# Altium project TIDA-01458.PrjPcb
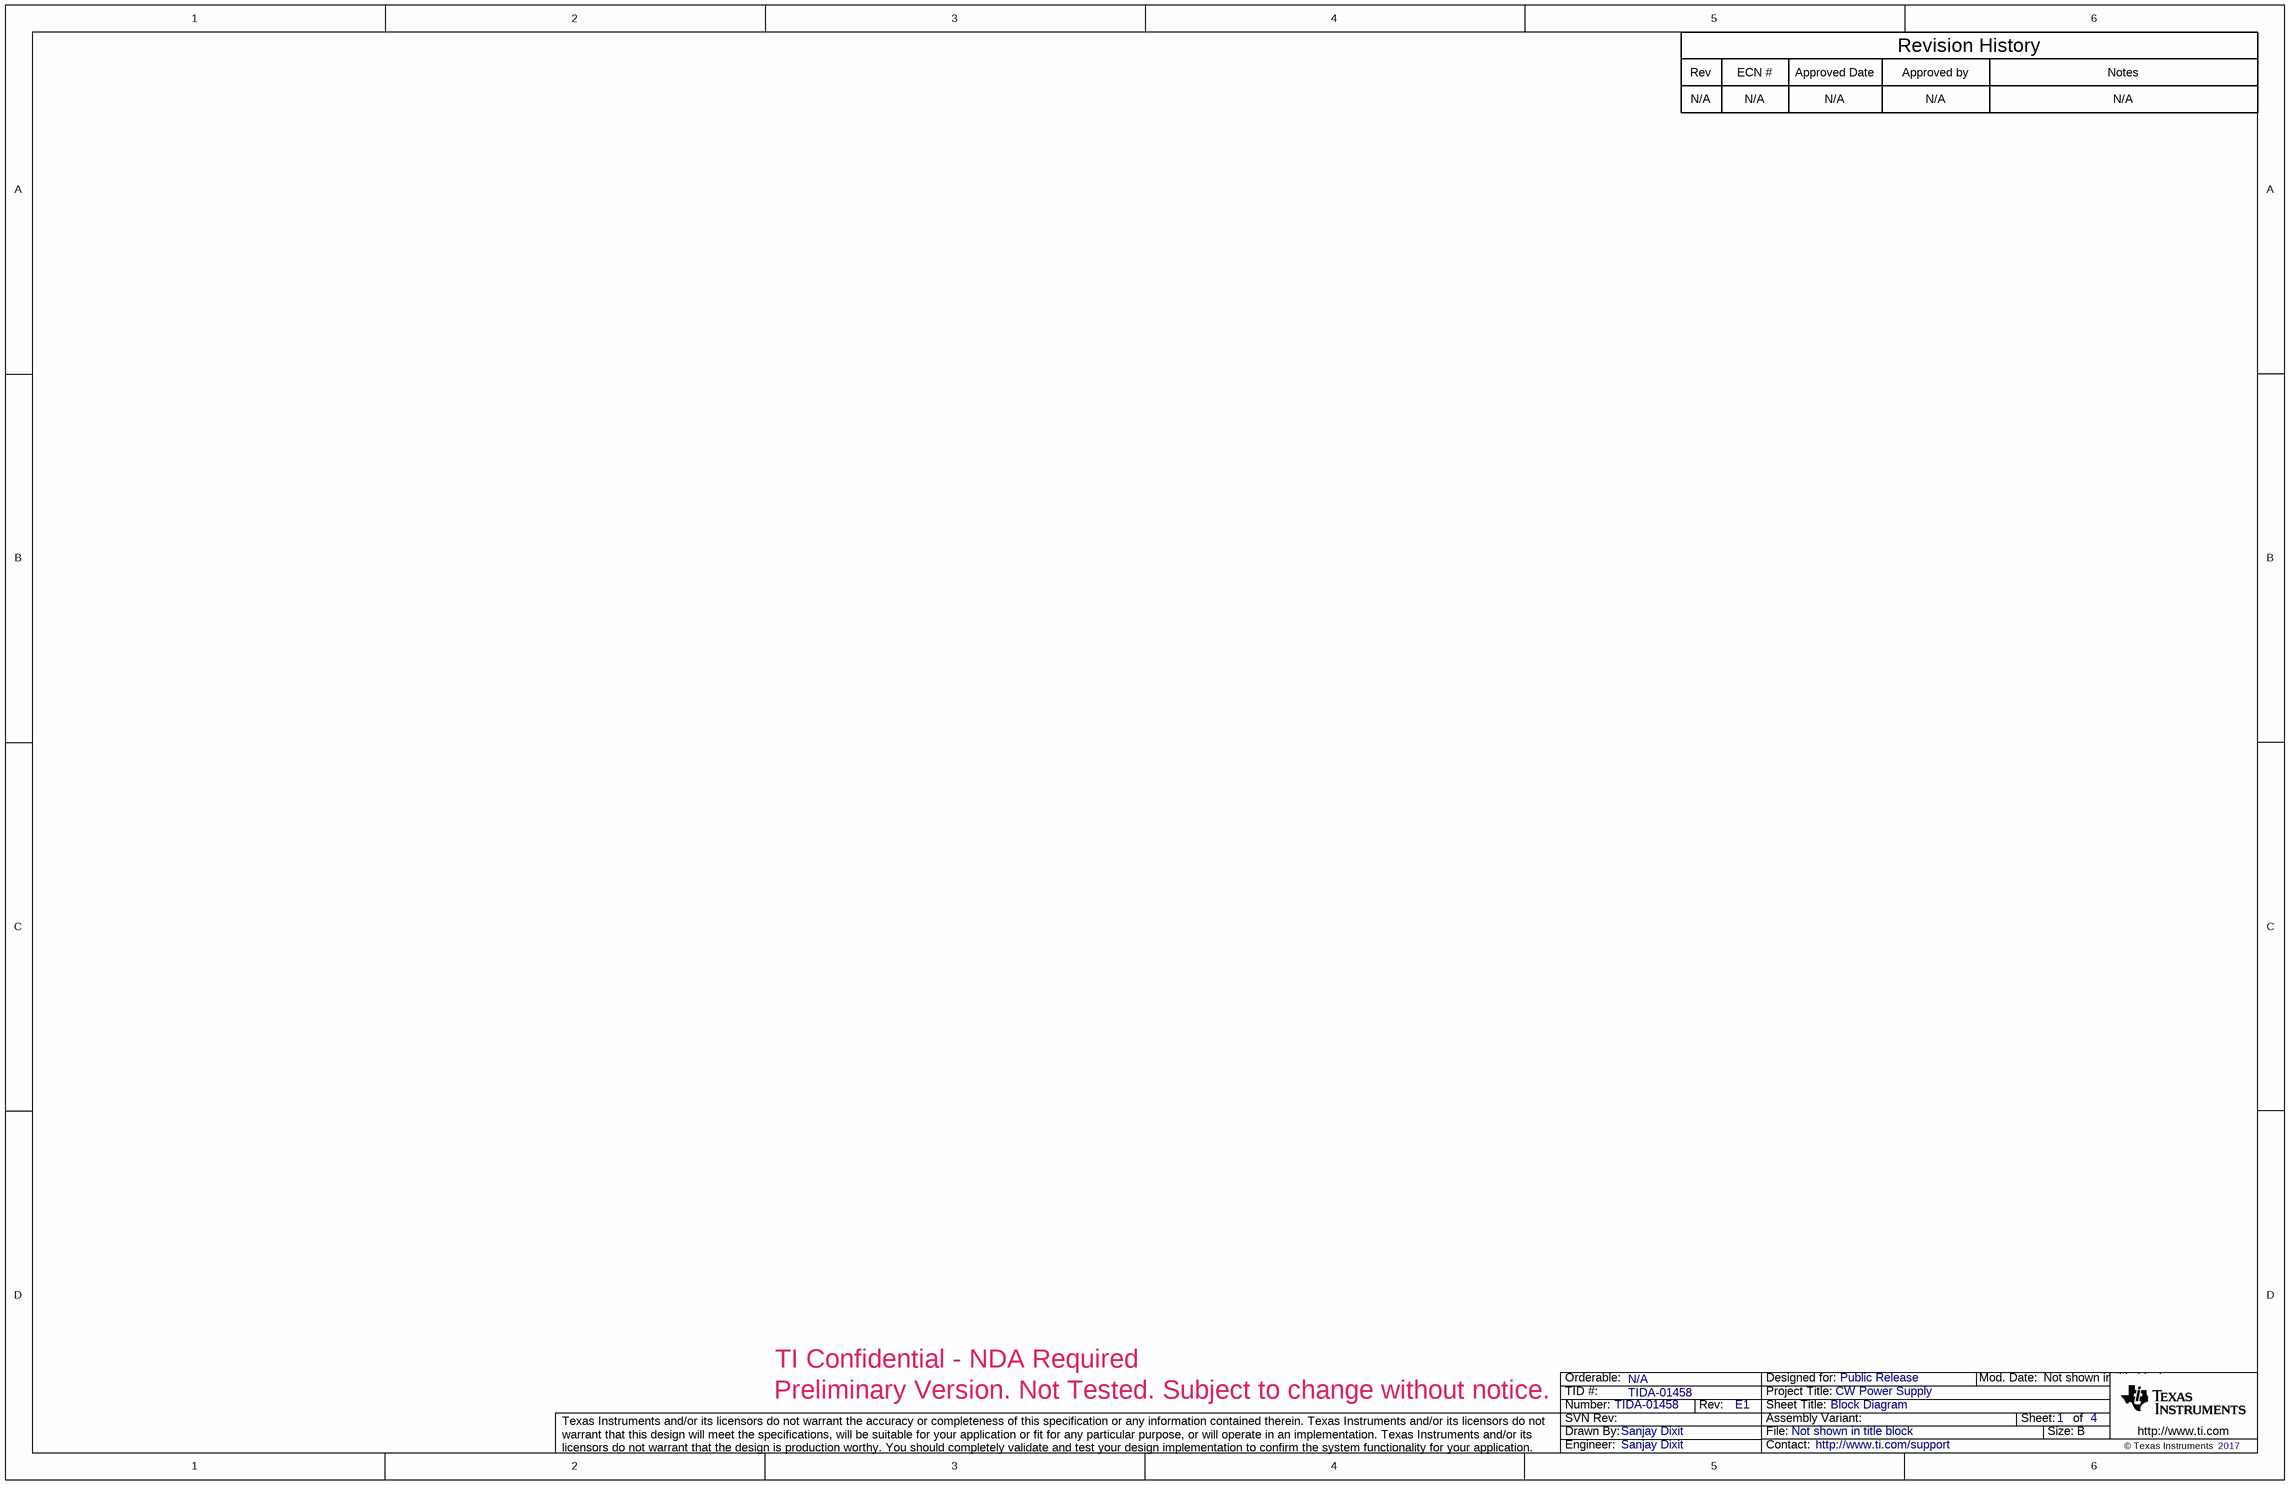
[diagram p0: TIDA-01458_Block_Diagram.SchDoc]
CopyrightYear: 2017; EVM_orderable: N/A; PCB_Layout: Akshay Labhe; PCB_Rev: E1; PRJ_Customer: Public Release; PRJ_Engineer: Sanjay Dixit; PRJ_Number: TIDA-01458; PRJ_Title: CW Power Supply; SCH_Rev: E1; TechSupport: http://www.ti.com/support; TID: TIDA-01458
4 sheets, 189 parts. Net scope: global (net labels, ports and power ports of the same name join across sheets).
Board file: TIDA-01458_PCB.PcbDoc
Sheets:
  TIDA-01458_Block_Diagram.SchDoc
  TIDA-01458-Sheet1.SchDoc
  TIDA-01458_Sheet2.SchDoc
  TIDA-01458_Hardware.SchDoc

## Sheet TIDA-01458_Block_Diagram.SchDoc: Block Diagram
size 431 x 279 mm; Date: Not shown in title block; ApprovedBy: Not shown in title block; CheckedBy: Not shown in title block; Author: Not shown in title block; CompanyName: Not shown in title block; DrawnBy: Sanjay Dixit; Engineer: Not shown in title block; Organization: Not shown in title block; Address1: Not shown in title block; Address2: Not shown in title block; Address3: Not shown in title block; Address4: Not shown in title block; DocumentNumber: 1; Revision: Use project parameter SCH_Rev; SheetNumber: 1; SheetTotal: 4; PageSetup: Record=PageOptions¦CenterHorizontal=True¦CenterVertical=True¦PrintScale=1.00¦XCorrection=1.00¦YCorrection=1.00¦PrintKind=0¦BorderSize=5000000¦LeftOffset=0¦BottomOffset=0¦Orientation=2¦PaperLength=1000¦PaperWidth=1000¦Scale=100¦PaperSource=15¦PrintQuality=600¦MediaType=1¦DitherType=10¦PaperKind=Letter¦PrintScaleMode=1

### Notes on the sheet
- Rev
- N/A
- ECN #
- Approved Date
- Approved by
- Revision History
- Notes
- TI Confidential - NDA Required
- Preliminary Version. Not Tested. Subject to change without notice.

## Sheet TIDA-01458-Sheet1.SchDoc: Sheet1
size 431 x 279 mm; Date: Not shown in title block; ApprovedBy: Not shown in title block; CheckedBy: Not shown in title block; Author: Not shown in title block; CompanyName: Not shown in title block; DrawnBy: Sanjay Dixit; Engineer: Not shown in title block; Organization: Not shown in title block; Address1: Not shown in title block; Address2: Not shown in title block; Address3: Not shown in title block; Address4: Not shown in title block; DocumentNumber: 1; Revision: Use project parameter SCH_Rev; SheetNumber: 2; SheetTotal: 4; PageSetup: Record=PageOptions¦CenterHorizontal=True¦CenterVertical=True¦PrintScale=1.00¦XCorrection=1.00¦YCorrection=1.00¦PrintKind=0¦BorderSize=5000000¦LeftOffset=0¦BottomOffset=0¦Orientation=2¦PaperLength=1000¦PaperWidth=1000¦Scale=100¦PaperSource=15¦PrintQuality=600¦MediaType=1¦DitherType=10¦PaperKind=Letter¦PrintScaleMode=1
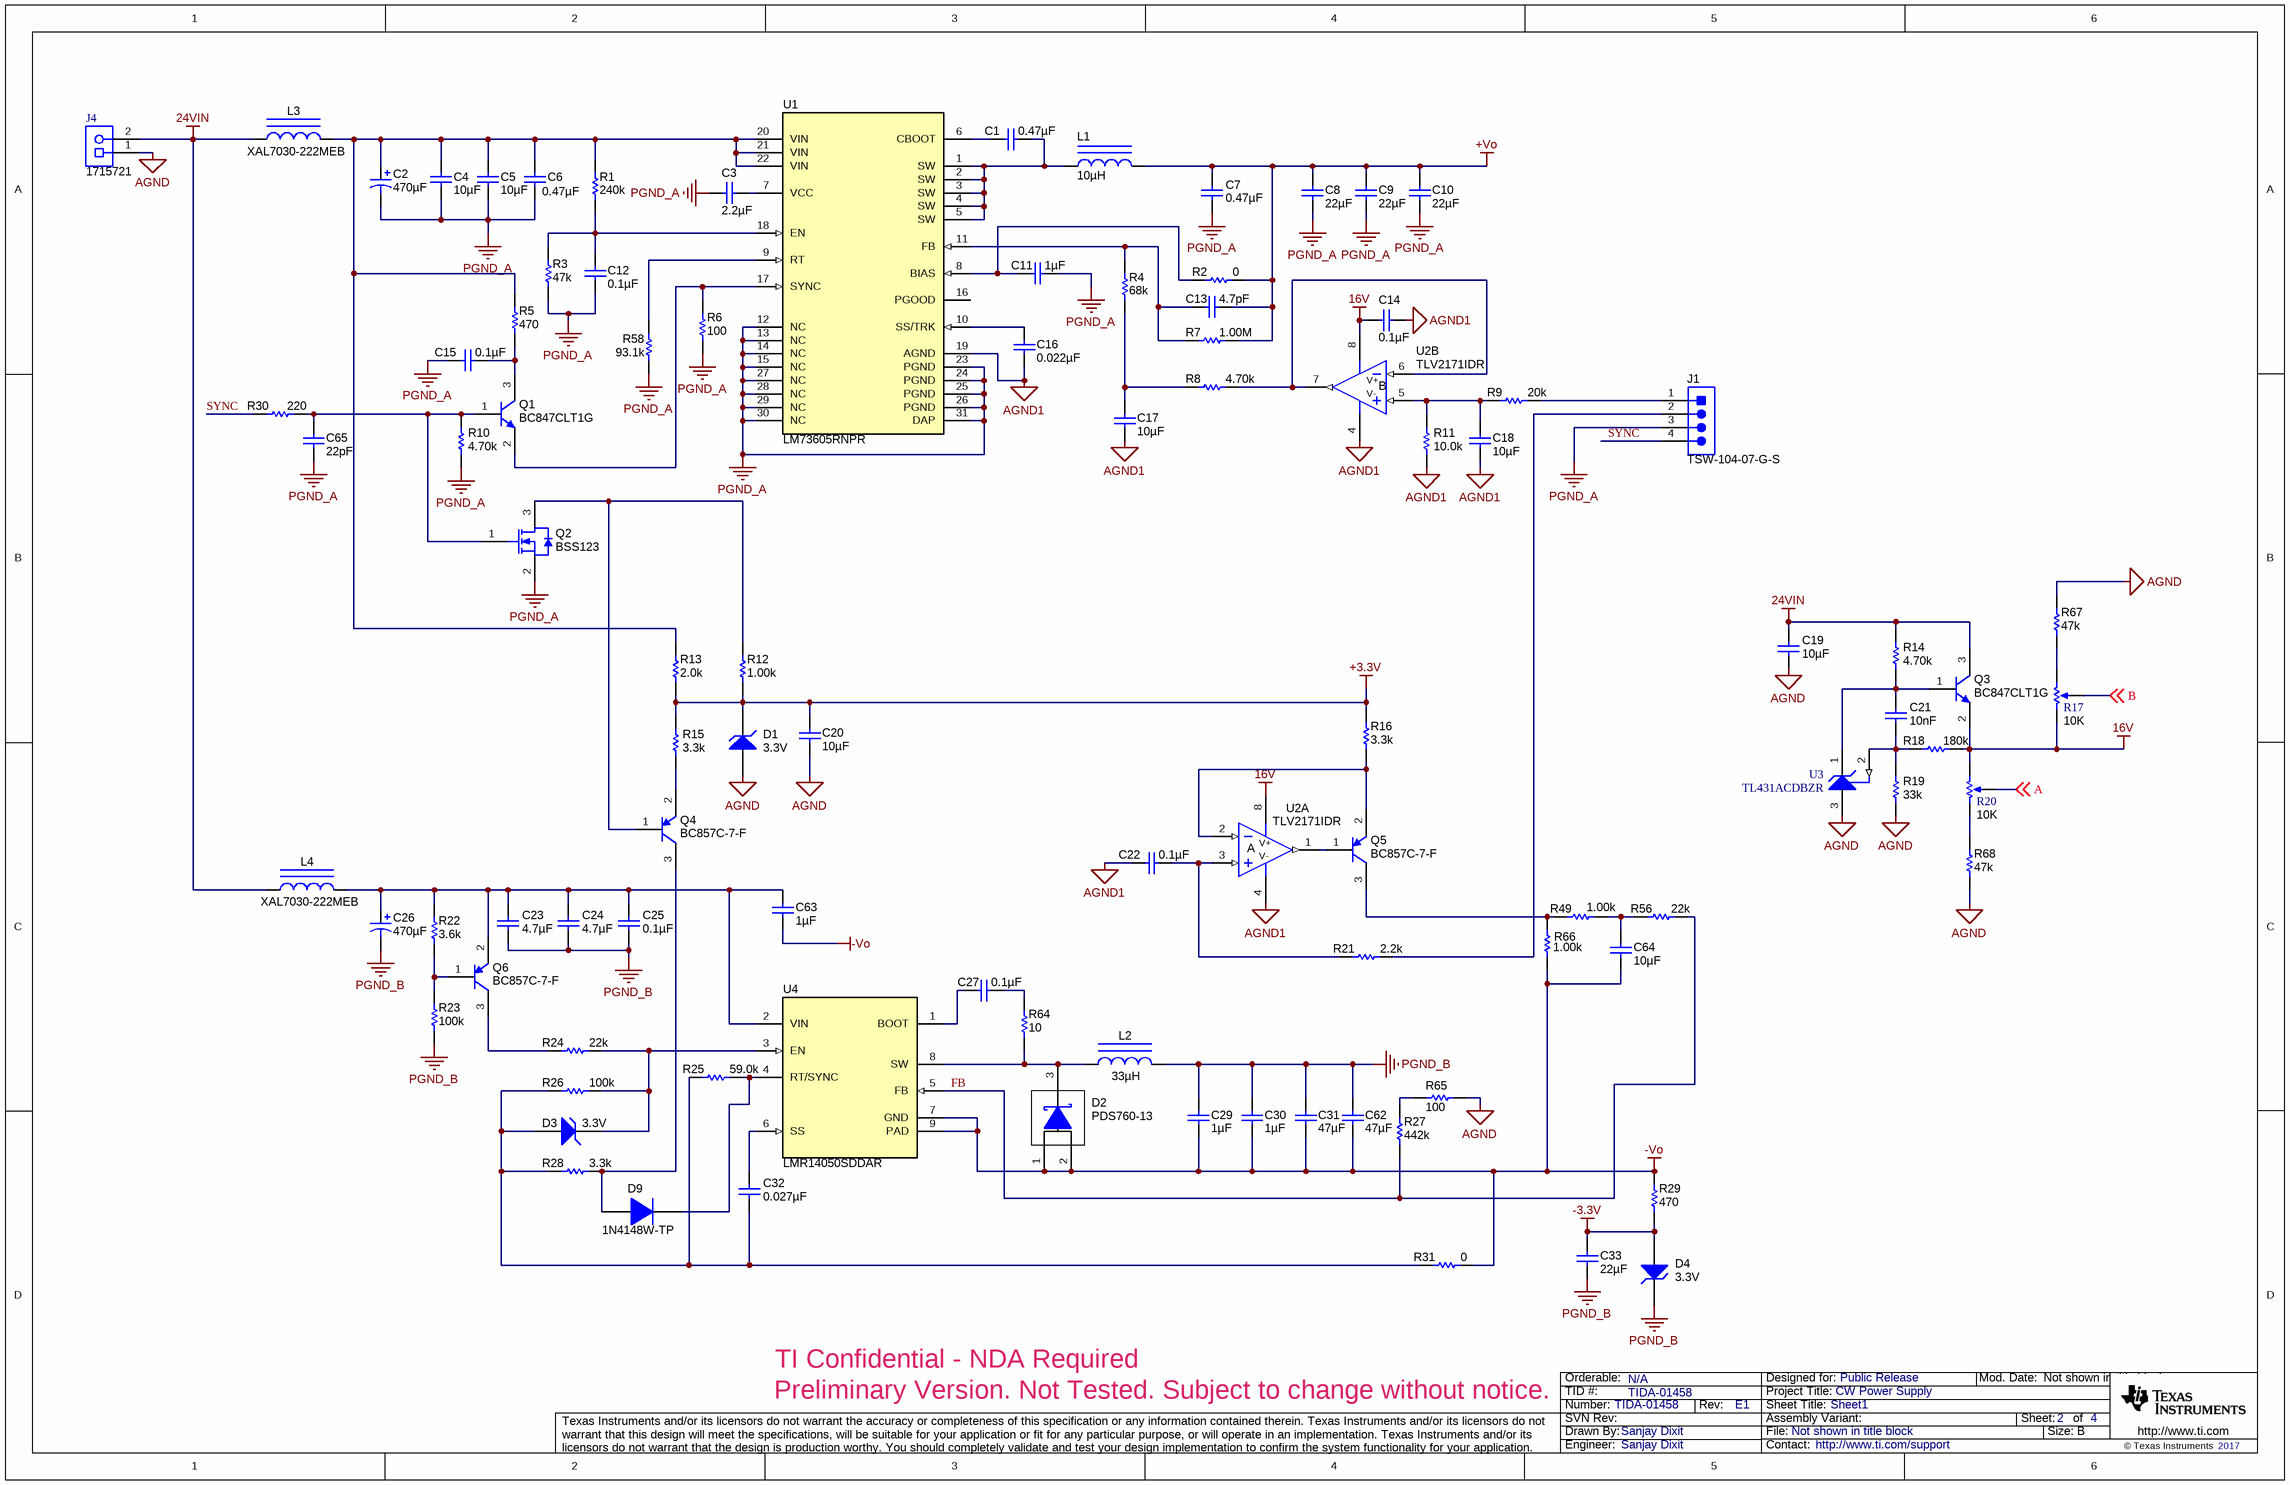
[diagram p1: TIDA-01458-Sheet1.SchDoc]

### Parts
C1  ValueDisplayed: 0.47µF  [0603]  (hidden comment: GRM188R61E474KA12D)
C2  ValueDisplayed: 470µF  [ZL_1000x2000]  (hidden comment: 35ZL470MEFC10X20)
C3  ValueDisplayed: 2.2µF  [0603]  (hidden comment: C1608X5R1V225K080AC)
C4  ValueDisplayed: 10µF  [1210_270]  (hidden comment: GRM32ER71H106KA12L)
C5  ValueDisplayed: 10µF  [1210_270]  (hidden comment: GRM32ER71H106KA12L)
C6  ValueDisplayed: 0.47µF  [0805_HV]  (hidden comment: GRM21BR71H474KA88L)
C7  ValueDisplayed: 0.47µF  [0805_HV]  (hidden comment: GRM21BR71H474KA88L)
C8  ValueDisplayed: 22µF  [1210_270]  (hidden comment: GRM32ER71E226KE15L)
C9  ValueDisplayed: 22µF  [1210_270]  (hidden comment: GRM32ER71E226KE15L)
C10  ValueDisplayed: 22µF  [1210_270]  (hidden comment: GRM32ER71E226KE15L)
C11  ValueDisplayed: 1µF  [0603]  (hidden comment: C1608X5R1H105K080AB)
C12  ValueDisplayed: 0.1µF  [0603]  (hidden comment: C1608X7R1H104K080AA)
C13  ValueDisplayed: 4.7pF  [0805_HV]  (hidden comment: 08055A4R7CAT2A)
C14  ValueDisplayed: 0.1µF  [0603]  (hidden comment: C1608X7R1H104K080AA)
C15  ValueDisplayed: 0.1µF  [0603]  (hidden comment: C1608X7R1H104K080AA)
C16  ValueDisplayed: 0.022µF  [0805_HV]  (hidden comment: 08055C223KAT2A)
C17  ValueDisplayed: 10µF  [1206_180]  (hidden comment: C3216X5R1H106K160AB)
C18  ValueDisplayed: 10µF  [1206_180]  (hidden comment: C3216X5R1H106K160AB)
C19  ValueDisplayed: 10µF  [1210_270]  (hidden comment: GRM32ER71H106KA12L)
C20  ValueDisplayed: 10µF  [1206_180]  (hidden comment: C3216X5R1H106K160AB)
C21  ValueDisplayed: 10nF  [1210_270]  (hidden comment: GRM32ER71H106KA12L)
C22  ValueDisplayed: 0.1µF  [0603]  (hidden comment: C1608X7R1H104K080AA)
C23  ValueDisplayed: 4.7µF  [1210_270]  (hidden comment: GRM32ER71H475KA88L)
C24  ValueDisplayed: 4.7µF  [1210_270]  (hidden comment: GRM32ER71H475KA88L)
C25  ValueDisplayed: 0.1µF  [0603]  (hidden comment: C1608X7R1H104K080AA)
C26  ValueDisplayed: 470µF  [ZL_1000x2000]  (hidden comment: 35ZL470MEFC10X20)
C27  ValueDisplayed: 0.1µF  [0603]  (hidden comment: C1608X7R1H104K080AA)
C29  ValueDisplayed: 1µF  [0805_HV]  (hidden comment: GRM21BR71E105KA99L)
C30  ValueDisplayed: 1µF  [0805_HV]  (hidden comment: GRM21BR71E105KA99L)
C31  ValueDisplayed: 47µF  [1206_190]  (hidden comment: C3216X5R1E476M160AC)
C32  ValueDisplayed: 0.027µF  [0603]  (hidden comment: GRM188R71E273KA01D)
C33  ValueDisplayed: 22µF  [1210_270]  (hidden comment: GRM32ER71E226KE15L)
C62  ValueDisplayed: 47µF  [1206_190]  (hidden comment: C3216X5R1E476M160AC)
C63  ValueDisplayed: 1µF  [0805_HV]  (hidden comment: GRM21BR71E105KA99L)
C64  ValueDisplayed: 10µF  [1206_180]  (hidden comment: C3216X5R1H106K160AB)
C65  ValueDisplayed: 22pF  [0603]  (hidden comment: 06035A220JAT2A)
D1  value 3.3V  [SMB]  (hidden comment: 1SMB5913BT3G)
D2  PDS760-13  [PowerDI5]
D3  value 3.3V  [SMB]  (hidden comment: 1SMB5913BT3G)
D4  value 3.3V  [SMB]  (hidden comment: 1SMB5913BT3G)
D9  1N4148W-TP  [SOD-123]
J1  TSW-104-07-G-S  [TSW-104-07-G-S]
J4  1715721  [PhoenixContact_1715721]
L1  ValueDisplayed: 10µH  [XAL7030]  (hidden comment: XAL7030-103MEB)
L2  ValueDisplayed: 33µH  [WE-HCA1]  (hidden comment: 7443551331)
L3  XAL7030-222MEB  [XAL7030]
L4  XAL7030-222MEB  [XAL7030]
Q1  BC847CLT1G  [SOT-23]
Q2  BSS123  [SOT-23]
Q3  BC847CLT1G  [SOT-23]
Q4  BC857C-7-F  [SOT-23]
Q5  BC857C-7-F  [SOT-23]
Q6  BC857C-7-F  [SOT-23]
R1  ValueDisplayed: 240k  [0805_HV]  (hidden comment: CRCW0805240KJNEA)
R2  ValueDisplayed: 0  [0603]  (hidden comment: CRCW06030000Z0EA)
R3  ValueDisplayed: 47k  [0805_HV]  (hidden comment: CRCW080547K0JNEA)
R4  ValueDisplayed: 68k  [0603]  (hidden comment: CRCW060368K0JNEA)
R5  ValueDisplayed: 470  [0603]  (hidden comment: CRCW0603470RJNEA)
R6  ValueDisplayed: 100  [0603]  (hidden comment: CRCW0603100RFKEA)
R7  ValueDisplayed: 1.00M  [0603]  (hidden comment: CRCW06031M00FKEA)
R8  ValueDisplayed: 4.70k  [0603]  (hidden comment: RC0603FR-074K7L)
R9  ValueDisplayed: 20k  [0603]  (hidden comment: CRCW060320K0JNEA)
R10  ValueDisplayed: 4.70k  [0603]  (hidden comment: RC0603FR-074K7L)
R11  ValueDisplayed: 10.0k  [0603]  (hidden comment: CRCW060310K0FKEA)
R12  ValueDisplayed: 1.00k  [0603]  (hidden comment: CRCW06031K00FKEA)
R13  ValueDisplayed: 2.0k  [0805_HV]  (hidden comment: CRCW08052K00JNEA)
R14  ValueDisplayed: 4.70k  [0603]  (hidden comment: RC0603FR-074K7L)
R15  ValueDisplayed: 3.3k  [0603]  (hidden comment: CRCW06033K30JNEA)
R16  ValueDisplayed: 3.3k  [0603]  (hidden comment: CRCW06033K30JNEA)
R17  value 10K  [Bourns_TC33X-2]  (hidden comment: TC33X-2-103E)
R18  ValueDisplayed: 180k  [0603]  (hidden comment: CRCW0603180KJNEA)
R19  ValueDisplayed: 33k  [0603]  (hidden comment: CRCW060333K0JNEA)
R20  value 10K  [Bourns_TC33X-2]  (hidden comment: TC33X-2-103E)
R21  ValueDisplayed: 2.2k  [0603]  (hidden comment: CRCW06032K20JNEA)
R22  ValueDisplayed: 3.6k  [0603]  (hidden comment: CRCW06033K60JNEA)
R23  ValueDisplayed: 100k  [0603]  (hidden comment: CRCW0603100KFKEA)
R24  ValueDisplayed: 22k  [0603]  (hidden comment: CRCW060322K0JNEA)
R25  ValueDisplayed: 59.0k  [0603]  (hidden comment: CRCW060359K0FKEA)
R26  ValueDisplayed: 100k  [0603]  (hidden comment: CRCW0603100KFKEA)
R27  ValueDisplayed: 442k  [0603]  (hidden comment: CRCW0603442KFKEA)
R28  ValueDisplayed: 3.3k  [0603]  (hidden comment: CRCW06033K30JNEA)
R29  ValueDisplayed: 470  [0805_HV]  (hidden comment: CRCW0805470RJNEA)
R30  ValueDisplayed: 220  [0603]  (hidden comment: CRCW0603220RJNEA)
R31  ValueDisplayed: 0  [0603]  (hidden comment: CRCW06030000Z0EA)
R49  ValueDisplayed: 1.00k  [0603]  (hidden comment: CRCW06031K00FKEA)
R56  ValueDisplayed: 22k  [0603]  (hidden comment: CRCW060322K0JNEA)
R58  ValueDisplayed: 93.1k  [0603]  (hidden comment: CRCW060393K1FKEA)
R64  ValueDisplayed: 10  [0603]  (hidden comment: CRCW060310R0JNEA)
R65  ValueDisplayed: 100  [0603]  (hidden comment: CRCW0603100RFKEA)
R66  ValueDisplayed: 1.00k  [0603]  (hidden comment: CRCW06031K00FKEA)
R67  ValueDisplayed: 47k  [0805_HV]  (hidden comment: CRCW080547K0JNEA)
R68  ValueDisplayed: 47k  [0805_HV]  (hidden comment: CRCW080547K0JNEA)
U1  LM73605RNPR  [RNP0030A]
U2  TLV2171IDR  [D0008A_N]  (parts A,B of 2)
U3  TL431ACDBZR  [DBZ0003A_N]
U4  LMR14050SDDAR  [DDA0008E_N]

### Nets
16V: C14.1 Q3.2(E) R17.3(CW) R18.2 R20.1(CCW) U2.8(V+)
24VIN: C19.1 J4.2 L3.1 L4.1 Q3.3(C) R14.2
+3.3V: C20.1 D1.1(K) R12.1 R13.1 R15.2 R16.2
+Vo: C7.2 C8.1 C9.1 C10.1 C13.2 L1.2 R2.1 R7.1
-3.3V: C33.1 D4.2(A) R29.1
-Vo: C29.2 C30.2 C31.2 C62.2 C63.2 C64.2 D2.1(A) D2.2(A) R29.2 R31.1 R66.1 U4.7(GND) U4.9(PAD)
AGND: C19.2 C20.2 D1.2(A) J4.1 R19.1 R65.2 R67.2 R68.1 U3.3(ANODE)
AGND1: C14.2 C16.1 C17.2 C18.2 C22.2 R11.1 U1.19(AGND) U2.4(V-)
PGND_A: C2.2(-) C3.1 C4.1 C5.1 C6.1 C7.1 C8.2 C9.2 C10.2 C11.1 C12.2 C15.2 C65.2 J1.3 Q2.2(S) R3.1 R6.1 R10.1 R58.2 U1.12(NC) U1.13(NC) U1.14(NC) U1.15(NC) U1.23(PGND) U1.24(PGND) U1.25(PGND) U1.26(PGND) U1.27(NC) U1.28(NC) U1.29(NC) U1.30(NC) U1.31(DAP)
PGND_B: C23.2 C24.2 C25.2 C26.2(-) C29.1 C30.1 C31.1 C33.2 C62.1 D4.1(K) L2.2 R23.1
A: R20.2(WIPER) ; off-sheet A
B: R17.2(WIPER) ; off-sheet B
FB: R27.1 R56.2 U4.5(FB)
SYNC: J1.4 R30.1
NetC1_1: C1.1 L1.1 U1.1(SW) U1.2(SW) U1.3(SW) U1.4(SW) U1.5(SW)
NetC1_2: C1.2 U1.6(CBOOT)
NetC2_1: C2.1(+) C4.2 C5.2 C6.2 L3.2 R1.2 R5.2 R13.2 U1.20(VIN) U1.21(VIN) U1.22(VIN)
NetC3_2: C3.2 U1.7(VCC)
NetC11_2: C11.2 R2.2 U1.8(BIAS)
NetC12_1: C12.1 R1.1 R3.2 U1.18(EN)
NetC13_1: C13.1 R4.2 R7.2 U1.11(FB)
NetC15_1: C15.1 Q1.3(C) R5.1
NetC16_2: C16.2 U1.10(SS/TRK)
NetC17_1: C17.1 R4.1 R8.2
NetC18_1: C18.1 R9.2 R11.2 U2.5(IN+)
NetC21_1: C21.1 Q3.1(B) R14.1 U3.1(CATHODE)
NetC21_2: C21.2 R18.1 R19.2 U3.2(REF)
NetC22_1: C22.1 R21.1 U2.3(IN+)
NetC23_1: C23.1 C24.1 C25.1 C26.1(+) C63.1 L4.2 Q6.2(E) R22.2 U4.2(VIN)
NetC27_1: C27.1 R64.2
NetC27_2: C27.2 U4.1(BOOT)
NetC32_1: C32.1 U4.6(SS)
NetC32_2: C32.2 D3.2(A) R25.1 R26.2 R28.1 R31.2
NetC64_1: C64.1 R49.2 R56.1
NetC65_1: C65.1 Q1.1(B) Q2.1(G) R10.2 R30.2
NetD2_3: D2.3(K) L2.1 R64.1 U4.8(SW)
NetD3_1: D3.1(K) R24.2 R26.1 U4.3(EN)
NetD9_1: D9.1(K) R25.2 U4.4(RT/SYNC)
NetD9_2: D9.2(A) Q4.3(C) R28.2
NetJ1_1: J1.1 R9.1
NetJ1_2: J1.2 R21.2
NetQ1_2: Q1.2(E) R6.2 U1.17(SYNC)
NetQ2_3: Q2.3(D) Q4.1(B) R12.2
NetQ4_2: Q4.2(E) R15.1
NetQ5_1: Q5.1(B) U2.1(OUT)
NetQ5_2: Q5.2(E) R16.1 U2.2(IN-)
NetQ5_3: Q5.3(C) R49.1 R66.2
NetQ6_1: Q6.1(B) R22.1 R23.2
NetQ6_3: Q6.3(C) R24.1
NetR8_1: R8.1 U2.6(IN-) U2.7(OUT)
NetR17_1: R17.1(CCW) R67.1
NetR20_3: R20.3(CW) R68.2
NetR27_2: R27.2 R65.1
NetR58_1: R58.1 U1.9(RT)

Not connected (* = marked no-connect by the designer): U1 16(PGOOD)

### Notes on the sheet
- TI Confidential - NDA Required
- Preliminary Version. Not Tested. Subject to change without notice.

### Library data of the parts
C1 = GRM188R61E474KA12D: CAP, CERM, 0.47 µF, 25 V, +/- 10%, X5R, 0603; Manufacturer: MuRata; Polarized: N; CompType: Capacitor; Value: 0.47uF; U/M: EA; Cap_F: 0.00000047; Tolerance_%: 10; Value1: Unknown; VDC_V: 25; Value2: 25V; TaMin_C: -55; TaMax_C: 85; SizeArea_mm2: 1.28; SizeAreaWB_mm2: 4.68; SizeX_mm: 1.6; SizeY_mm: 0.8; SizeZ_mm: 1; AEC Category: Q200
C2 C26 = 35ZL470MEFC10X20: CAP, AL, 470 µF, 35 V, +/- 20%, TH; Manufacturer: Rubycon; Polarized: Y; CompType: Capacitor; Value: 470uF; U/M: EA; Cap_F: 0.00047; Tolerance_%: 20; Value1: Unknown; VDC_V: 35; Value2: 35V; TaMin_C: -40; TaMax_C: 105; Cap_Case: 10x20; SizeAreaWB_mm2: 144; SizeArea_mm2: 100; SizeX_mm: 10; SizeZ_mm: 22; AEC Category: Q200; AEC Qualified: N; Green_Lifecycle: Not Set; Green_REACh: Incomplete
C3 = C1608X5R1V225K080AC: CAP, CERM, 2.2 µF, 35 V, +/- 10%, X5R, 0603; Manufacturer: TDK; Polarized: N; CompType: Capacitor; Value: 2.2uF; U/M: EA; Cap_F: 0.0000022; Tolerance_%: 10; ESR_ohm: 0.007674; Value1: 0.007674 ohm; VDC_V: 35; Value2: 35V; IRMS_A: 1.87823; TaMin_C: -55; TaMax_C: 85; SizeArea_mm2: 1.28; SizeAreaWB_mm2: 4.68; SizeX_mm: 1.6; SizeY_mm: 0.8; SizeZ_mm: 1; AEC Category: Q200; Green_Lifecycle: Active; Green_REACh: Passed
C4 C5 C19 C21 = GRM32ER71H106KA12L: CAP, CERM, 10 µF, 50 V, +/- 10%, X7R, 1210; Manufacturer: MuRata; Polarized: N; CompType: Capacitor; Value: 10uF; U/M: EA; Cap_F: 0.00001; Tolerance_%: 10; Value1: Unknown; VDC_V: 50; Value2: 50V; TaMin_C: -55; TaMax_C: 125; Cap_Case: 1210; SizeArea_mm2: 8; SizeAreaWB_mm2: 14.7; SizeX_mm: 3.2; SizeY_mm: 2.5; SizeZ_mm: 2.7; AEC Category: Q200
C6 C7 = GRM21BR71H474KA88L: CAP, CERM, 0.47 µF, 50 V, +/- 10%, X7R, 0805; Manufacturer: MuRata; Polarized: N; CompType: Capacitor; Value: 0.47uF; U/M: EA; Cap_F: 0.00000047; Tolerance_%: 10; Value1: Unknown; VDC_V: 50; Value2: 50V; TaMin_C: -55; TaMax_C: 125; Cap_Case: 0805; SizeArea_mm2: 2.5; SizeAreaWB_mm2: 6.75; SizeX_mm: 2; SizeY_mm: 1.25; SizeZ_mm: 1.45; AEC Category: Q200
C8-C10 C33 = GRM32ER71E226KE15L: CAP, CERM, 22 µF, 25 V, +/- 10%, X7R, 1210; Manufacturer: MuRata; Polarized: N; CompType: Capacitor; Value: 22uF; U/M: EA; Cap_F: 0.000022; Tolerance_%: 10; ESR_ohm: 0.002334; Value1: 0.002334 ohm; VDC_V: 25; Value2: 25V; IRMS_A: 3.832999; TaMin_C: -55; TaMax_C: 125; Cap_Case: 1210; SizeArea_mm2: 8; SizeAreaWB_mm2: 14.7; SizeX_mm: 3.2; SizeY_mm: 2.5; SizeZ_mm: 2.7; AEC Category: Q200; Green_Lifecycle: Active; Green_REACh: Passed
C11 = C1608X5R1H105K080AB: CAP, CERM, 1 µF, 50 V, +/- 10%, X5R, 0603; Manufacturer: TDK; Polarized: N; CompType: Capacitor; Value: 1uF; U/M: EA; Cap_F: 0.000001; Tolerance_%: 10; ESR_ohm: 0.005522; Value1: 0.005522 ohm; VDC_V: 50; Value2: 50V; IRMS_A: 2.21617; TaMin_C: -55; TaMax_C: 85; SizeArea_mm2: 1.28; SizeAreaWB_mm2: 4.68; SizeX_mm: 1.6; SizeY_mm: 0.8; SizeZ_mm: 1; AEC Category: Q200
C12 C14 C15 C22 C25 C27 = C1608X7R1H104K080AA: CAP, CERM, 0.1 µF, 50 V, +/- 10%, X7R, 0603; Manufacturer: TDK; Polarized: N; CompType: Capacitor; Value: 0.1uF; U/M: EA; Cap_F: 0.0000001; Tolerance_%: 10; ESR_ohm: 0.0296; Value1: 0.0296 ohm; VDC_V: 50; Value2: 50V; IRMS_A: 0.97199; TaMin_C: -55; TaMax_C: 125; SizeArea_mm2: 1.28; SizeAreaWB_mm2: 4.68; SizeX_mm: 1.6; SizeY_mm: 0.8; SizeZ_mm: 1; AEC Category: Q200
C13 = 08055A4R7CAT2A: CAP, CERM, 4.7 pF, 50 V, +/- 5%, C0G/NP0, 0805; Manufacturer: AVX; Polarized: N; CompType: Capacitor; Value: 4.7pF; U/M: EA; Cap_F: 0.0000000000047; Tolerance_%: 5; ESR_ohm: 2.668; Value1: 2.668 ohm; VDC_V: 50; Value2: 50V; TaMin_C: -55; TaMax_C: 125; Cap_Case: 0805; SizeArea_mm2: 2.5; SizeAreaWB_mm2: 6.75; SizeX_mm: 2; SizeY_mm: 1.25; SizeZ_mm: 1.45; AEC Category: Q200
C16 = 08055C223KAT2A: CAP, CERM, 0.022 µF, 50 V, +/- 10%, X7R, 0805; Manufacturer: AVX; Polarized: N; CompType: Capacitor; Value: 0.022uF; U/M: EA; Cap_F: 0.000000022; Tolerance_%: 10; ESR_ohm: 0.052; Value1: 0.052 ohm; VDC_V: 50; Value2: 50V; TaMin_C: -55; TaMax_C: 125; Cap_Case: 0805; AEC Category: Q200
C17 C18 C20 C64 = C3216X5R1H106K160AB: CAP, CERM, 10 µF, 50 V,+/- 10%, X5R, 1206; Manufacturer: TDK; Polarized: N; CompType: Capacitor; Value: 10uF; U/M: EA; Cap_F: 0.00001; Tolerance_%: 10; ESR_ohm: 0.002229; Value1: 0.002229 ohm; VDC_V: 50; Value2: 50V; IRMS_A: 4.85932; TaMin_C: -55; TaMax_C: 85; Cap_Case: 1206; SizeArea_mm2: 5.12; SizeAreaWB_mm2: 10.92; SizeX_mm: 3.2; SizeY_mm: 1.6; SizeZ_mm: 1.8; AEC Category: Q200; Green_Lifecycle: Active; Green_REACh: Passed
C23 C24 = GRM32ER71H475KA88L: CAP, CERM, 4.7 µF, 50 V, +/- 10%, X7R, 1210; Manufacturer: MuRata; Polarized: N; CompType: Capacitor; Value: 4.7uF; U/M: EA; Cap_F: 0.0000047; Tolerance_%: 10; ESR_ohm: 0.002; Value1: 0.002 ohm; VDC_V: 50; Value2: 50V; TaMin_C: -55; TaMax_C: 125; Cap_Case: 1210; SizeArea_mm2: 8; SizeAreaWB_mm2: 14.7; SizeX_mm: 3.2; SizeY_mm: 2.5; SizeZ_mm: 2.7; AEC Category: Q200
C29 C30 C63 = GRM21BR71E105KA99L: CAP, CERM, 1 µF, 25 V, +/- 10%, X7R, 0805; Manufacturer: MuRata; Polarized: N; CompType: Capacitor; Value: 1uF; U/M: EA; Cap_F: 0.000001; Tolerance_%: 10; Value1: Unknown; VDC_V: 25; Value2: 25V; TaMin_C: -55; TaMax_C: 125; Cap_Case: 0805; SizeArea_mm2: 2.5; SizeAreaWB_mm2: 6.75; SizeX_mm: 2; SizeY_mm: 1.25; SizeZ_mm: 1.45; AEC Category: Q200
C31 C62 = C3216X5R1E476M160AC: CAP, CERM, 47 µF, 25 V, +/- 20%, X5R, 1206_190; Manufacturer: TDK; Polarized: N; CompType: Capacitor; Value: 47uF; U/M: EA; Cap_F: 0.000047; Tolerance_%: 20; Value1: Unknown; VDC_V: 25; Value2: 25V; TaMin_C: -55; TaMax_C: 85; Cap_Case: 1206; SizeArea_mm2: 5.12; SizeAreaWB_mm2: 10.92; SizeX_mm: 3.2; SizeY_mm: 1.6; SizeZ_mm: 1.9; AEC Category: Q200; Green_Lifecycle: Active; Green_REACh: Passed
C32 = GRM188R71E273KA01D: CAP, CERM, 0.027 µF, 25 V, +/- 10%, X7R, 0603; Manufacturer: MuRata; Polarized: N; CompType: Capacitor; Value: 0.027uF; U/M: EA; Cap_F: 0.000000027; Tolerance_%: 10; Value1: Unknown; VDC_V: 25; Value2: 25V; TaMin_C: -55; TaMax_C: 125; SizeArea_mm2: 1.28; SizeAreaWB_mm2: 4.68; SizeX_mm: 1.6; SizeY_mm: 0.8; SizeZ_mm: 1; AEC Category: Q200
C65 = 06035A220JAT2A: CAP, CERM, 22 pF, 50 V,+/- 5%, C0G/NP0, 0603; Manufacturer: AVX; Polarized: N; CompType: Capacitor; Value: 22pF; U/M: EA; Cap_F: 0.000000000022; Tolerance_%: 5; ESR_ohm: 0.259; Value1: 0.259 ohm; VDC_V: 50; Value2: 50V; TaMin_C: -55; TaMax_C: 125; SizeArea_mm2: 1.28; SizeAreaWB_mm2: 4.68; SizeX_mm: 1.6; SizeY_mm: 0.8; SizeZ_mm: 1; AEC Category: Q200; Green_Lifecycle: Active; Green_REACh: Passed
D1 D3 D4 = 1SMB5913BT3G: Diode, Zener, 3.3 V, 550 mW, SMB; Manufacturer: ON Semiconductor; SymbolCreator: a0412235; U/M: EA; Power_W: 0.55; Vz_V: 3.3; Value1: 0.55W; RJA_CperW: 226; SizeAreaWB_mm2: 44.156; SizeArea_mm2: 21.336; SizeX_mm: 5.6; SizeY_mm: 3.81; SizeZ_mm: 2.6; AEC Category: Q101
D2 = PDS560-13: Diode, Schottky, 60 V, 7 A, PowerDI5; Manufacturer: Diodes Inc.; U/M: EA; Vf_V: 0.67; Value: 60V; Value1: 7A; Value2: 0.67V; Io_A: 5; Vr_V: 60; TJmax_C: 150; SizeAreaWB_mm2: 49.56; SizeArea_mm2: 24.96; SizeX_mm: 6.4; SizeY_mm: 3.9; SizeZ_mm: 1.05; AEC Category: Q101; Green_Lifecycle: Active; Green_REACh: Passed
D9 = 1N4148W-TP: Diode, Switching, 100 V, 0.15 A, SOD-123; Manufacturer: Micro Commercial Components; U/M: EA; Vf_V: 1.25; Value: 100V; Value1: 0.15A; Value2: 1.25V; Io_A: 0.15; Vr_V: 100; TJmax_C: 150; SizeAreaWB_mm2: 13.095; SizeArea_mm2: 6.545; SizeX_mm: 3.85; SizeY_mm: 1.7; SizeZ_mm: 1.35; AEC Category: Q101; Green_Lifecycle: Not Set; Green_REACh: Incomplete
J1 = TSW-104-07-G-S: Header, 100mil, 4x1, Gold, TH; Manufacturer: Samtec; SymbolCreator: a0412235; Pitch_mm: 2.54; Gender: Male; Shrouded: N; Row_Count: 1; Current_A: 6.3; Voltage_V: 550; Cert_CSA: Y
J4 = 1715721: Terminal Block, 5.08 mm, 2x1, TH; Manufacturer: Phoenix Contact; SymbolCreator: a0412235; Pitch_mm: 5.08; Gender: Female; Row_Count: 1; ContactFinish: Tin; Current_A: 17.5; Voltage_V: 400; Cert_CSA: Y; Cert_CULUS: N
L1 = XAL7030-103MEB: Inductor, Shielded, Composite, 10 µH, 5.3 A, 0.057 ohm, SMD; Manufacturer: Coilcraft; Value: 10uH; Ind_H: 10.0E-6; Imax_A: 5.3; Irms: 5.3A @ 40C rise; Isat: 7A @ 30% inductance drop; DCR_ohm: 0.057; Value2: 5.3A; SizeAreaWB_mm2: 100; SizeArea_mm2: 64; SizeX_mm: 8; SizeZ_mm: 3.1; AEC Category: Q200; Green_Lifecycle: Not Set; Green_REACh: Incomplete
L2 = 7443551331: Inductor, Shielded Drum Core, WE-Perm, 33uH, 5.5A, 0.0305 ohm, SMD; Manufacturer: Wurth Elektronik eiSos; Ind_H: 33.0E-6; Imax_A: 5.5; Irms: 5.5A @ 50C rise; Isat: 5.5A @ 30% inductance drop; DCR_ohm: 0.0305; U/M: EA
L3 L4 = XAL7030-222MEB: Inductor, Shielded, Composite, 2.2uH, 12.9A, 0.0137 ohm, SMD; Manufacturer: Coilcraft; ValueDisplayed: 2.2µH; Ind_H: 2.2E-6; Imax_A: 12.9; Irms: 12.9A @ 40C rise; Isat: 18A @ 0.7% inductance drop; DCR_ohm: 0.0137
Q1 Q3 = BC847CLT1G, ON Semiconductor: Transistor, NPN, 45 V, 0.1 A, SOT-23; CompType: BJT; PNP: 0; NPN: 1; Vceo_V: 45; Vcesat1_V: 0.7; Value: 45 V; IcRated_A: 0.1; Value1: 0.1 A; HfeMax: 800; TaMin_C: -55; TaMax_C: 150; SizeAreaWB_mm2: 14; SizeArea_mm2: 7.5; SizeX_mm: 2.5; SizeY_mm: 3; SizeZ_mm: 1.1; U/M: EA; AEC Category: Q101
Q2 = BSS123: MOSFET, N-CH, 100 V, 0.17 A, SOT-23; Manufacturer: Fairchild Semiconductor; Alternate Manufacturer: None; U/M: EA; ChType: N; Value: 100V; VdsMax_V: 100; Value1: 10 ohm; Rdson45_ohm: 10; Value2: 1.8 nC; QgTyp_nC: 1.8; Vgs_V: 20; IdsMax_A: 0.17; AEC Category: Q101
Q4-Q6 = BC857C-7-F, Diodes Inc.: Transistor, PNP, 45 V, 0.1 A, SOT-23; CompType: BJT; PNP: 1; NPN: 0; Vceo_V: 45; Vcesat1_V: 0.075; Value: 45 V; IcRated_A: 0.1; Value1: 0.1 A; HfeMax: 600; TaMin_C: -65; TaMax_C: 150; U/M: EA; AEC Category: Q101
R1 = CRCW0805240KJNEA: RES, 240 k, 5%, 0.125 W, 0805; Manufacturer: Vishay-Dale; CompType: Resistor; Value: 240k; Res_ohm: 240000; Tolerance_%: 5; Power_W: 0.125; Value2: 0.125W; VDC_V: 150; TempCo: 200 ppm/C; SizeArea_mm2: 2.5; SizeX_mm: 2; SizeY_mm: 1.25; SizeZ_mm: 1.45; EIA_Code: E24; U/M: EA; AEC Category: Q200
R2 R31 = CRCW06030000Z0EA: RES, 0, 5%, 0.1 W, 0603; Manufacturer: Vishay-Dale; CompType: Resistor; Value: 0; Value_Code: 0000; Tolerance_%: 5; Power_W: 0.1; Value2: 0.1W; VDC_V: 75; TempCo: 200 ppm/C; SizeArea_mm2: 1.28; SizeX_mm: 1.6; SizeY_mm: 0.8; SizeZ_mm: 1; EIA_Code: E24; U/M: EA; AEC Category: Q200; Green_Lifecycle: Active; Green_REACh: Passed
R3 R67 R68 = CRCW080547K0JNEA: RES, 47 k, 5%, 0.125 W, 0805; Manufacturer: Vishay-Dale; CompType: Resistor; Value: 47k; Res_ohm: 47000; Value_Code: 47k0; Tolerance_%: 5; Power_W: 0.125; Value2: 0.125W; VDC_V: 150; TempCo: 200 ppm/C; SizeArea_mm2: 2.5; SizeX_mm: 2; SizeY_mm: 1.25; SizeZ_mm: 1.45; EIA_Code: E24; U/M: EA; AEC Category: Q200
R4 = CRCW060368K0JNEA: RES, 68 k, 5%, 0.1 W, 0603; Manufacturer: Vishay-Dale; CompType: Resistor; Value: 68k; Res_ohm: 68000; Value_Code: 68k0; Tolerance_%: 5; Power_W: 0.1; Value2: 0.1W; VDC_V: 75; TempCo: 200 ppm/C; EIA_Code: E24; U/M: EA; AEC Category: Q200
R5 = CRCW0603470RJNEA: RES, 470, 5%, 0.1 W, 0603; Manufacturer: Vishay-Dale; CompType: Resistor; Value: 470; Value_Code: 470R; Tolerance_%: 5; Power_W: 0.1; Value2: 0.1W; VDC_V: 75; TempCo: 200 ppm/C; SizeArea_mm2: 1.28; SizeX_mm: 1.6; SizeY_mm: 0.8; SizeZ_mm: 1; EIA_Code: E24; U/M: EA; AEC Category: Q200; Green_Lifecycle: Active; Green_REACh: Passed
R6 R65 = CRCW0603100RFKEA: RES, 100, 1%, 0.1 W, 0603; Manufacturer: Vishay-Dale; CompType: Resistor; Value: 100; Value_Code: 100R; Tolerance_%: 1; Power_W: 0.1; Value2: 0.1W; VDC_V: 75; TempCo: 100 ppm/C; SizeArea_mm2: 1.28; SizeX_mm: 1.6; SizeY_mm: 0.8; EIA_Code: E96; U/M: EA; AEC Category: Q200; Green_Lifecycle: Active; Green_REACh: Passed
R7 = CRCW06031M00FKEA: RES, 1.00 M, 1%, 0.1 W, 0603; Manufacturer: Vishay-Dale; CompType: Resistor; Value: 1.00Meg; Res_ohm: 1000000; Value_Code: 1M00; Tolerance_%: 1; Power_W: 0.1; Value2: 0.1W; VDC_V: 75; TempCo: 100 ppm/C; SizeArea_mm2: 1.28; SizeX_mm: 1.6; SizeY_mm: 0.8; EIA_Code: E96; U/M: EA; AEC Category: Q200; Green_Lifecycle: Active; Green_REACh: Passed
R8 R10 R14 = RC0603FR-074K7L: RES, 4.70 k, 1%, 0.1 W, 0603; Manufacturer: Yageo America; CompType: Resistor; Value: 4.70k; Res_ohm: 4700; Value_Code: 4k70; Tolerance_%: 1; Power_W: 0.1; Value2: 0.1W; VDC_V: 150; TempCo: 200 ppm/C; SizeArea_mm2: 1.28; SizeX_mm: 1.6; SizeY_mm: 0.8; U/M: EA; AEC Category: Q200; Green_Lifecycle: Active; Green_REACh: Passed
R9 = CRCW060320K0JNEA: RES, 20 k, 5%, 0.1 W, 0603; Manufacturer: Vishay-Dale; CompType: Resistor; Value: 20k; Res_ohm: 20000; Value_Code: 20k0; Tolerance_%: 5; Power_W: 0.1; Value2: 0.1W; VDC_V: 75; TempCo: 200 ppm/C; EIA_Code: E24; U/M: EA; AEC Category: Q200
R11 = CRCW060310K0FKEA: RES, 10.0 k, 1%, 0.1 W, 0603; Manufacturer: Vishay-Dale; CompType: Resistor; Value: 10.0k; Res_ohm: 10000; Value_Code: 10k0; Tolerance_%: 1; Power_W: 0.1; Value2: 0.1W; VDC_V: 75; TempCo: 100 ppm/C; SizeArea_mm2: 1.28; SizeX_mm: 1.6; SizeY_mm: 0.8; EIA_Code: E96; U/M: EA; AEC Category: Q200; Green_Lifecycle: Active; Green_REACh: Passed
R12 R49 R66 = CRCW06031K00FKEA: RES, 1.00 k, 1%, 0.1 W, 0603; Manufacturer: Vishay-Dale; CompType: Resistor; Value: 1.00k; Res_ohm: 1000; Value_Code: 1k00; Tolerance_%: 1; Power_W: 0.1; Value2: 0.1W; VDC_V: 75; TempCo: 100 ppm/C; SizeArea_mm2: 1.28; SizeX_mm: 1.6; SizeY_mm: 0.8; EIA_Code: E96; U/M: EA; AEC Category: Q200; Green_Lifecycle: Active; Green_REACh: Passed
R13 = CRCW08052K00JNEA: RES, 2.0 k, 5%, 0.125 W, 0805; Manufacturer: Vishay-Dale; CompType: Resistor; Value: 2.0k; Res_ohm: 2000; Value_Code: 2k00; Tolerance_%: 5; Power_W: 0.125; Value2: 0.125W; VDC_V: 150; TempCo: 200 ppm/C; SizeArea_mm2: 2.5; SizeX_mm: 2; SizeY_mm: 1.25; SizeZ_mm: 1.45; EIA_Code: E24; U/M: EA; AEC Category: Q200; Green_Lifecycle: Active; Green_REACh: Passed
R15 R28 = CRCW06033K30JNEA: RES, 3.3 k, 5%, 0.1 W, 0603; Manufacturer: Vishay-Dale; CompType: Resistor; Value: 3.3k; Res_ohm: 3300; Value_Code: 3k30; Tolerance_%: 5; Power_W: 0.1; Value2: 0.1W; VDC_V: 75; TempCo: 200 ppm/C; EIA_Code: E24; U/M: EA; AEC Category: Q200
R16 = CRCW06033K30JNEA: RES, 3.3 k, 5%, 0.1 W, 0603; Manufacturer: Vishay-Dale; CompType: Resistor; Value: 3.3k; Res_ohm: 3300; Value_Code: 3k30; Tolerance_%: 5; Power_W: 0.1; Value2: 0.1W; VDC_V: 75; TempCo: 200 ppm/C; SizeArea_mm2: 1.28; SizeX_mm: 1.6; SizeY_mm: 0.8; SizeZ_mm: 1; EIA_Code: E24; U/M: EA; AEC Category: Q200; Green_Lifecycle: Active; Green_REACh: Passed
R17 R20 = TC33X-2-103E: TRIMMER 10K OHM 0.1W; Manufacturer: Bourns; Sim Note: Enter the Resistance value and the set point into parameter fields.; SymbolCreator: a0412235; CompType: Potentiometer; SizeAreaWB_mm2: 22.08; SizeArea_mm2: 13.68; SizeX_mm: 3.8; SizeY_mm: 3.6; SizeZ_mm: 1.5
R18 = CRCW0603180KJNEA: RES, 180 k, 5%, 0.1 W, 0603; Manufacturer: Vishay-Dale; CompType: Resistor; Value: 180k; Res_ohm: 180000; Tolerance_%: 5; Power_W: 0.1; Value2: 0.1W; VDC_V: 75; TempCo: 200 ppm/C; SizeArea_mm2: 1.28; SizeX_mm: 1.6; SizeY_mm: 0.8; SizeZ_mm: 1; EIA_Code: E24; U/M: EA; AEC Category: Q200
R19 = CRCW060333K0JNEA: RES, 33 k, 5%, 0.1 W, 0603; Manufacturer: Vishay-Dale; CompType: Resistor; Value: 33k; Res_ohm: 33000; Value_Code: 33k0; Tolerance_%: 5; Power_W: 0.1; Value2: 0.1W; VDC_V: 75; TempCo: 200 ppm/C; SizeArea_mm2: 1.28; SizeX_mm: 1.6; SizeY_mm: 0.8; SizeZ_mm: 1; EIA_Code: E24; U/M: EA; AEC Category: Q200; Green_Lifecycle: Active; Green_REACh: Passed
R21 = CRCW06032K20JNEA: RES, 2.2 k, 5%, 0.1 W, 0603; Manufacturer: Vishay-Dale; CompType: Resistor; Value: 2.2k; Res_ohm: 2200; Value_Code: 2k20; Tolerance_%: 5; Power_W: 0.1; Value2: 0.1W; VDC_V: 75; TempCo: 200 ppm/C; EIA_Code: E24; U/M: EA; AEC Category: Q200
R22 = CRCW06033K60JNEA: RES, 3.6 k, 5%, 0.1 W, 0603; Manufacturer: Vishay-Dale; CompType: Resistor; Value: 3.6k; Res_ohm: 3600; Value_Code: 3k60; Tolerance_%: 5; Power_W: 0.1; Value2: 0.1W; VDC_V: 75; TempCo: 200 ppm/C; SizeArea_mm2: 1.28; SizeX_mm: 1.6; SizeY_mm: 0.8; SizeZ_mm: 1; EIA_Code: E24; U/M: EA; AEC Category: Q200
R23 R26 = CRCW0603100KFKEA: RES, 100 k, 1%, 0.1 W, 0603; Manufacturer: Vishay-Dale; CompType: Resistor; Value: 100k; Res_ohm: 100000; Tolerance_%: 1; Power_W: 0.1; Value2: 0.1W; VDC_V: 75; TempCo: 100 ppm/C; SizeArea_mm2: 1.28; SizeX_mm: 1.6; SizeY_mm: 0.8; EIA_Code: E96; U/M: EA; AEC Category: Q200; Green_Lifecycle: Active; Green_REACh: Passed
R24 = CRCW060322K0JNEA: RES, 22 k, 5%, 0.1 W, 0603; Manufacturer: Vishay-Dale; CompType: Resistor; Value: 22k; Res_ohm: 22000; Value_Code: 22k0; Tolerance_%: 5; Power_W: 0.1; Value2: 0.1W; VDC_V: 75; TempCo: 200 ppm/C; EIA_Code: E24; U/M: EA; AEC Category: Q200
R25 = CRCW060359K0FKEA: RES, 59.0 k, 1%, 0.1 W, 0603; Manufacturer: Vishay-Dale; CompType: Resistor; Value: 59.0k; Res_ohm: 59000; Value_Code: 59k0; Tolerance_%: 1; Power_W: 0.1; Value2: 0.1W; VDC_V: 75; TempCo: 100 ppm/C; SizeArea_mm2: 1.28; SizeX_mm: 1.6; SizeY_mm: 0.8; EIA_Code: E96; U/M: EA; AEC Category: Q200; Green_Lifecycle: Active; Green_REACh: Passed
R27 = CRCW0603442KFKEA: RES, 442 k, 1%, 0.1 W, 0603; Manufacturer: Vishay-Dale; CompType: Resistor; Value: 442k; Res_ohm: 442000; Tolerance_%: 1; Power_W: 0.1; Value2: 0.1W; VDC_V: 75; TempCo: 100 ppm/C; SizeArea_mm2: 1.28; SizeX_mm: 1.6; SizeY_mm: 0.8; EIA_Code: E96; U/M: EA; AEC Category: Q200; Green_Lifecycle: Active; Green_REACh: Passed
R29 = CRCW0805470RJNEA: RES, 470, 5%, 0.125 W, 0805; Manufacturer: Vishay-Dale; CompType: Resistor; Value: 470; Value_Code: 470R; Tolerance_%: 5; Power_W: 0.125; Value2: 0.125W; VDC_V: 150; TempCo: 200 ppm/C; SizeArea_mm2: 2.5; SizeX_mm: 2; SizeY_mm: 1.25; SizeZ_mm: 1.45; EIA_Code: E24; U/M: EA; AEC Category: Q200
R30 = CRCW0603220RJNEA: RES, 220, 5%, 0.1 W, 0603; Manufacturer: Vishay-Dale; CompType: Resistor; Value: 220; Value_Code: 220R; Tolerance_%: 5; Power_W: 0.1; Value2: 0.1W; VDC_V: 75; TempCo: 200 ppm/C; SizeArea_mm2: 1.28; SizeX_mm: 1.6; SizeY_mm: 0.8; SizeZ_mm: 1; EIA_Code: E24; U/M: EA; AEC Category: Q200; Green_Lifecycle: Active; Green_REACh: Passed
R56 = CRCW060322K0JNEA: RES, 22 k, 5%, 0.1 W, 0603; Manufacturer: Vishay-Dale; CompType: Resistor; Value: 22k; Res_ohm: 22000; Value_Code: 22k0; Tolerance_%: 5; Power_W: 0.1; Value2: 0.1W; VDC_V: 75; TempCo: 200 ppm/C; SizeArea_mm2: 1.28; SizeX_mm: 1.6; SizeY_mm: 0.8; SizeZ_mm: 1; EIA_Code: E24; U/M: EA; AEC Category: Q200; Green_Lifecycle: Active; Green_REACh: Passed
R58 = CRCW060393K1FKEA: RES, 93.1 k, 1%, 0.1 W, 0603; Manufacturer: Vishay-Dale; CompType: Resistor; Value: 93.1k; Res_ohm: 93100; Value_Code: 93k1; Tolerance_%: 1; Power_W: 0.1; Value2: 0.1W; VDC_V: 75; TempCo: 100 ppm/C; SizeArea_mm2: 1.28; SizeX_mm: 1.6; SizeY_mm: 0.8; EIA_Code: E96; U/M: EA; AEC Category: Q200
R64 = CRCW060310R0JNEA: RES, 10, 5%, 0.1 W, 0603; Manufacturer: Vishay-Dale; CompType: Resistor; Value: 10; Value_Code: 10R0; Tolerance_%: 5; Power_W: 0.1; Value2: 0.1W; VDC_V: 75; TempCo: 200 ppm/C; SizeArea_mm2: 1.28; SizeX_mm: 1.6; SizeY_mm: 0.8; SizeZ_mm: 1; EIA_Code: E24; U/M: EA; AEC Category: Q200; Green_Lifecycle: Active; Green_REACh: Passed
U1 = LM73605RNPR: 3.5V to 36V 5A Synchronous Step-Down Voltage Regulator, RNP0030A (WQFN-30); Alternate PartNumber: LM73605RNPRT; Manufacturer: Texas Instruments; SymbolCreator: a0411947; SizeArea_mm2: 24; SizeAreaWB_mm2: 48; SizeX_mm: 4; SizeY_mm: 6; SizeZ_mm: 0.8; CompType: IC; U/M: EA
U2 = TLV2171IDR: 36V, Low Power, RRO, General Purpose Operational Amplifier, D0008A (SOIC-8); Manufacturer: Texas Instruments; CompType: IC; SizeArea_mm2: 30.38; SizeAreaWB_mm2: 56.58; SizeX_mm: 4.9; SizeY_mm: 6.2; SizeZ_mm: 1.75; U/M: EA
U3 = TL431ACDBZR: Adjustable Precision Shunt Regulator, 34 ppm / degC, 100 mA, 0 to 70 degC, 3-pin SOT-23 (DBZ), Green (RoHS & no Sb/Br); Manufacturer: Texas Instruments; Alternate PartNumber: Equivalent; Initial Accuracy @ 25/deg C(%): 1; Iout/Iz(Max)(mA): 100; Min Iz for Regulation(uA): 600; Rating: Catalog; SubFamily: Shunt Voltage Reference; Temp Coeff(Typ)(ppm/ degree C): 34; VO Adj(Max)(V): 36; VO Adj(Min)(V): 2.495
U4 = LMR14050SDDAR: 40V, 5A SIMPLE SWITCHER, 2.2MHz Step-Down Regulator with 40uA IQ, DDA0008E (SOIC-8); Manufacturer: Texas Instruments; SymbolCreator: Altium; SizeArea_mm2: 31; SizeAreaWB_mm2: 57.4; SizeX_mm: 5; SizeY_mm: 6.2; SizeZ_mm: 1.7; CompType: IC; U/M: EA

## Sheet TIDA-01458_Sheet2.SchDoc: Sheet2
size 431 x 279 mm; Date: Not shown in title block; ApprovedBy: Not shown in title block; CheckedBy: Not shown in title block; Author: Not shown in title block; CompanyName: Not shown in title block; DrawnBy: Sanjay Dixit; Engineer: Not shown in title block; Organization: Not shown in title block; Address1: Not shown in title block; Address2: Not shown in title block; Address3: Not shown in title block; Address4: Not shown in title block; DocumentNumber: 1; Revision: Use project parameter SCH_Rev; SheetNumber: 3; SheetTotal: 4; PageSetup: Record=PageOptions¦CenterHorizontal=True¦CenterVertical=True¦PrintScale=1.00¦XCorrection=1.00¦YCorrection=1.00¦PrintKind=0¦BorderSize=5000000¦LeftOffset=0¦BottomOffset=0¦Orientation=2¦PaperLength=1000¦PaperWidth=1000¦Scale=100¦PaperSource=15¦PrintQuality=600¦MediaType=1¦DitherType=10¦PaperKind=Letter¦PrintScaleMode=1
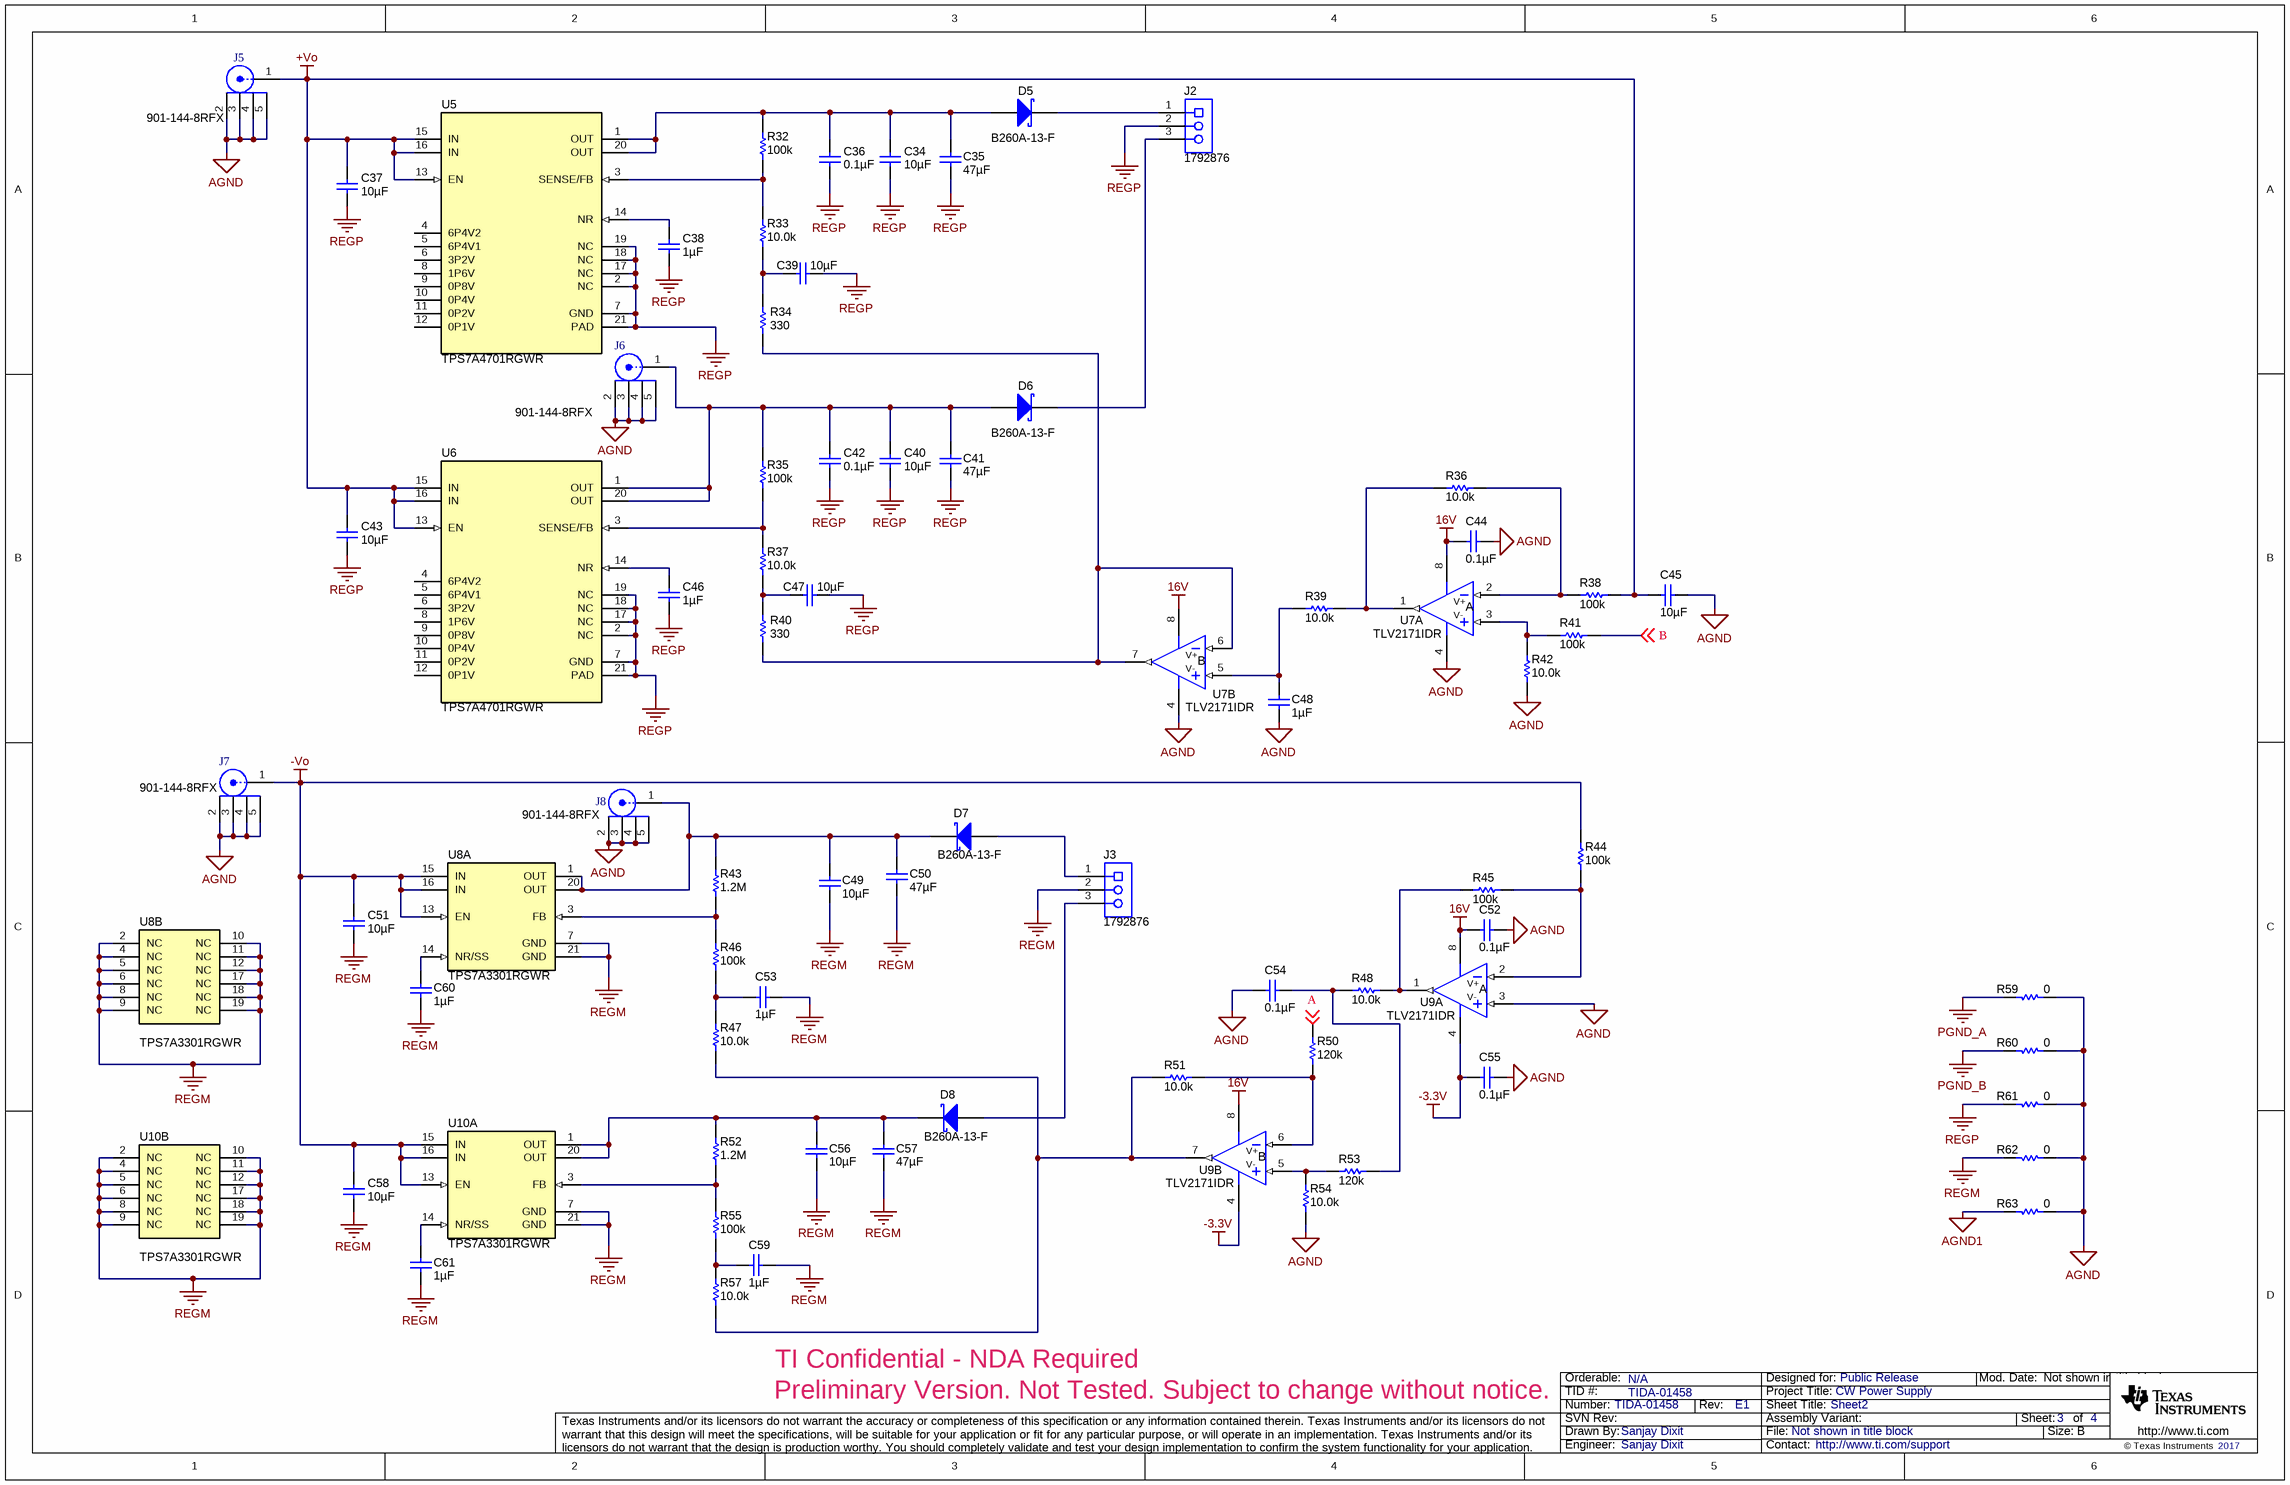
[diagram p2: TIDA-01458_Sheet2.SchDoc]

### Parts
C34  ValueDisplayed: 10µF  [0805_HV]  (hidden comment: C2012X5R1V106K085AC)
C35  ValueDisplayed: 47µF  [1206_190]  (hidden comment: C3216X5R1E476M160AC)
C36  ValueDisplayed: 0.1µF  [0603]  (hidden comment: C1608X7R1H104K080AA)
C37  ValueDisplayed: 10µF  [0805_HV]  (hidden comment: C2012X5R1V106K085AC)
C38  ValueDisplayed: 1µF  [0603]  (hidden comment: C1608X5R1H105K080AB)
C39  ValueDisplayed: 10µF  [0805_HV]  (hidden comment: C2012X5R1V106K085AC)
C40  ValueDisplayed: 10µF  [0805_HV]  (hidden comment: C2012X5R1V106K085AC)
C41  ValueDisplayed: 47µF  [1206_190]  (hidden comment: C3216X5R1E476M160AC)
C42  ValueDisplayed: 0.1µF  [0603]  (hidden comment: C1608X7R1H104K080AA)
C43  ValueDisplayed: 10µF  [0805_HV]  (hidden comment: C2012X5R1V106K085AC)
C44  ValueDisplayed: 0.1µF  [0603]  (hidden comment: C1608X7R1H104K080AA)
C45  ValueDisplayed: 10µF  [0805_HV]  (hidden comment: C2012X5R1V106K085AC)
C46  ValueDisplayed: 1µF  [0603]  (hidden comment: C1608X5R1H105K080AB)
C47  ValueDisplayed: 10µF  [0805_HV]  (hidden comment: C2012X5R1V106K085AC)
C48  ValueDisplayed: 1µF  [0603]  (hidden comment: C1608X5R1H105K080AB)
C49  ValueDisplayed: 10µF  [0805_HV]  (hidden comment: C2012X5R1V106K085AC)
C50  ValueDisplayed: 47µF  [1206_190]  (hidden comment: C3216X5R1E476M160AC)
C51  ValueDisplayed: 10µF  [0805_HV]  (hidden comment: C2012X5R1V106K085AC)
C52  ValueDisplayed: 0.1µF  [0603]  (hidden comment: C1608X7R1H104K080AA)
C53  ValueDisplayed: 1µF  [0603]  (hidden comment: C1608X5R1H105K080AB)
C54  ValueDisplayed: 0.1µF  [0603]  (hidden comment: C1608X7R1H104K080AA)
C55  ValueDisplayed: 0.1µF  [0603]  (hidden comment: C1608X7R1H104K080AA)
C56  ValueDisplayed: 10µF  [0805_HV]  (hidden comment: C2012X5R1V106K085AC)
C57  ValueDisplayed: 47µF  [1206_190]  (hidden comment: C3216X5R1E476M160AC)
C58  ValueDisplayed: 10µF  [0805_HV]  (hidden comment: C2012X5R1V106K085AC)
C59  ValueDisplayed: 1µF  [0603]  (hidden comment: C1608X5R1H105K080AB)
C60  ValueDisplayed: 1µF  [0603]  (hidden comment: C1608X5R1H105K080AB)
C61  ValueDisplayed: 1µF  [0603]  (hidden comment: C1608X5R1H105K080AB)
D5  B260A-13-F  [SMA]
D6  B260A-13-F  [SMA]
D7  B260A-13-F  [SMA]
D8  B260A-13-F  [SMA]
J2  1792876  [Phoenix_1792876]
J3  1792876  [Phoenix_1792876]
J5  901-144-8RFX  [Amphenol_901-144-8RFX]
J6  901-144-8RFX  [Amphenol_901-144-8RFX]
J7  901-144-8RFX  [Amphenol_901-144-8RFX]
J8  901-144-8RFX  [Amphenol_901-144-8RFX]
R32  ValueDisplayed: 100k  [0603]  (hidden comment: CRCW0603100KFKEA)
R33  ValueDisplayed: 10.0k  [0603]  (hidden comment: CRCW060310K0FKEA)
R34  ValueDisplayed: 330  [0603]  (hidden comment: CRCW0603330RJNEA)
R35  ValueDisplayed: 100k  [0603]  (hidden comment: CRCW0603100KFKEA)
R36  ValueDisplayed: 10.0k  [0603]  (hidden comment: CRCW060310K0FKEA)
R37  ValueDisplayed: 10.0k  [0603]  (hidden comment: CRCW060310K0FKEA)
R38  ValueDisplayed: 100k  [0603]  (hidden comment: CRCW0603100KFKEA)
R39  ValueDisplayed: 10.0k  [0603]  (hidden comment: CRCW060310K0FKEA)
R40  ValueDisplayed: 330  [0603]  (hidden comment: CRCW0603330RJNEA)
R41  ValueDisplayed: 100k  [0603]  (hidden comment: CRCW0603100KFKEA)
R42  ValueDisplayed: 10.0k  [0603]  (hidden comment: CRCW060310K0FKEA)
R43  ValueDisplayed: 1.2M  [0603]  (hidden comment: CRCW06031M20JNEA)
R44  ValueDisplayed: 100k  [0603]  (hidden comment: CRCW0603100KFKEA)
R45  ValueDisplayed: 100k  [0603]  (hidden comment: CRCW0603100KFKEA)
R46  ValueDisplayed: 100k  [0603]  (hidden comment: CRCW0603100KFKEA)
R47  ValueDisplayed: 10.0k  [0603]  (hidden comment: CRCW060310K0FKEA)
R48  ValueDisplayed: 10.0k  [0603]  (hidden comment: CRCW060310K0FKEA)
R50  ValueDisplayed: 120k  [0603]  (hidden comment: CRCW0603120KJNEA)
R51  ValueDisplayed: 10.0k  [0603]  (hidden comment: CRCW060310K0FKEA)
R52  ValueDisplayed: 1.2M  [0603]  (hidden comment: CRCW06031M20JNEA)
R53  ValueDisplayed: 120k  [0603]  (hidden comment: CRCW0603120KJNEA)
R54  ValueDisplayed: 10.0k  [0603]  (hidden comment: CRCW060310K0FKEA)
R55  ValueDisplayed: 100k  [0603]  (hidden comment: CRCW0603100KFKEA)
R57  ValueDisplayed: 10.0k  [0603]  (hidden comment: CRCW060310K0FKEA)
R59  ValueDisplayed: 0  [0603]  (hidden comment: CRCW06030000Z0EA)
R60  ValueDisplayed: 0  [0603]  (hidden comment: CRCW06030000Z0EA)
R61  ValueDisplayed: 0  [0603]  (hidden comment: CRCW06030000Z0EA)
R62  ValueDisplayed: 0  [0603]  (hidden comment: CRCW06030000Z0EA)
R63  ValueDisplayed: 0  [0603]  (hidden comment: CRCW06030000Z0EA)
U5  TPS7A4701RGWR  [RGW0020A]
U6  TPS7A4701RGWR  [RGW0020A]
U7  TLV2171IDR  [D0008A_N]  (parts A,B of 2)
U8  TPS7A3301RGWR  [RGW0020A]  (parts A,B of 2)
U9  TLV2171IDR  [D0008A_N]  (parts A,B of 2)
U10  TPS7A3301RGWR  [RGW0020A]  (parts A,B of 2)

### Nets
16V: C44.1 C52.1 U7.8(V+) U9.8(V+)
+Vo: C37.2 C43.2 C45.2 J5.1 R38.2 U5.13(EN) U5.15(IN) U5.16(IN) U6.13(EN) U6.15(IN) U6.16(IN)
-3.3V: C55.1 U9.4(V-)
-Vo: C51.2 C58.2 J7.1 R44.2 U8.13(EN) U8.15(IN) U8.16(IN) U10.13(EN) U10.15(IN) U10.16(IN)
AGND: C44.2 C45.1 C48.1 C52.2 C54.1 C55.2 J5.2 J5.3 J5.4 J5.5 J6.2 J6.3 J6.4 J6.5 J7.2 J7.3 J7.4 J7.5 J8.2 J8.3 J8.4 J8.5 R42.1 R54.1 R59.2 R60.2 R61.2 R62.2 R63.2 U7.4(V-) U9.3(IN+)
AGND1: R63.1
PGND_A: R59.1
PGND_B: R60.1
REGM: C49.1 C50.2 C51.1 C53.1 C56.1 C57.2 C58.1 C59.1 C60.1 C61.1 J3.2 R62.1 U8.2(NC) U8.4(NC) U8.5(NC) U8.6(NC) U8.7(GND) U8.8(NC) U8.9(NC) U8.10(NC) U8.11(NC) U8.12(NC) U8.17(NC) U8.18(NC) U8.19(NC) U8.21(GND) U10.2(NC) U10.4(NC) U10.5(NC) U10.6(NC) U10.7(GND) U10.8(NC) U10.9(NC) U10.10(NC) U10.11(NC) U10.12(NC) U10.17(NC) U10.18(NC) U10.19(NC) U10.21(GND)
REGP: C34.1 C35.2 C36.2 C37.1 C38.1 C39.1 C40.1 C41.2 C42.2 C43.1 C46.1 C47.1 J2.2 R61.1 U5.2(NC) U5.7(GND) U5.17(NC) U5.18(NC) U5.19(NC) U5.21(PAD) U6.2(NC) U6.7(GND) U6.17(NC) U6.18(NC) U6.19(NC) U6.21(PAD)
A: R50.2 ; off-sheet A
B: R41.2 ; off-sheet B
NetC34_2: C34.2 C35.1 C36.1 D5.2(A) R32.1 U5.1(OUT) U5.20(OUT)
NetC38_2: C38.2 U5.14(NR)
NetC39_2: C39.2 R33.2 R34.2
NetC40_2: C40.2 C41.1 C42.1 D6.2(A) J6.1 R35.1 U6.1(OUT) U6.20(OUT)
NetC46_2: C46.2 U6.14(NR)
NetC47_2: C47.2 R37.2 R40.2
NetC48_2: C48.2 R39.1 U7.5(IN+)
NetC49_2: C49.2 C50.1 D7.1(K) J8.1 R43.2 U8.1(OUT) U8.20(OUT)
NetC53_2: C53.2 R46.2 R47.1
NetC54_2: C54.2 R48.2 R53.1
NetC56_2: C56.2 C57.1 D8.1(K) R52.2 U10.1(OUT) U10.20(OUT)
NetC59_2: C59.2 R55.2 R57.1
NetC60_2: C60.2 U8.14(NR/SS)
NetC61_2: C61.2 U10.14(NR/SS)
NetD5_1: D5.1(K) J2.1
NetD6_1: D6.1(K) J2.3
NetD7_2: D7.2(A) J3.1
NetD8_2: D8.2(A) J3.3
NetR32_2: R32.2 R33.1 U5.3(SENSE/FB)
NetR34_1: R34.1 R40.1 U7.6(IN-) U7.7(OUT)
NetR35_2: R35.2 R37.1 U6.3(SENSE/FB)
NetR36_1: R36.1 R39.2 U7.1(OUT)
NetR36_2: R36.2 R38.1 U7.2(IN-)
NetR41_1: R41.1 R42.2 U7.3(IN+)
NetR43_1: R43.1 R46.1 U8.3(FB)
NetR44_1: R44.1 R45.2 U9.2(IN-)
NetR45_1: R45.1 R48.1 U9.1(OUT)
NetR47_2: R47.2 R51.1 R57.2 U9.7(OUT)
NetR50_1: R50.1 R51.2 U9.6(IN-)
NetR52_1: R52.1 R55.1 U10.3(FB)
NetR53_2: R53.2 R54.2 U9.5(IN+)

Not connected (* = marked no-connect by the designer): U5 4(6P4V2) 5(6P4V1) 6(3P2V) 8(1P6V) 9(0P8V) 10(0P4V) 11(0P2V) 12(0P1V); U6 4(6P4V2) 5(6P4V1) 6(3P2V) 8(1P6V) 9(0P8V) 10(0P4V) 11(0P2V) 12(0P1V)

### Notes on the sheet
- TI Confidential - NDA Required
- Preliminary Version. Not Tested. Subject to change without notice.

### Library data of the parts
C34 C37 C39 C40 C43 C45 C47 C49 C51 C56 C58 = C2012X5R1V106K085AC: CAP, CERM, 10 µF, 35 V, +/- 10%, X5R, 0805; Manufacturer: TDK; Polarized: N; CompType: Capacitor; Value: 10uF; U/M: EA; Cap_F: 0.00001; Tolerance_%: 10; ESR_ohm: 0.002818; Value1: 0.002818 ohm; VDC_V: 35; Value2: 35V; IRMS_A: 3.88676; TaMin_C: -55; TaMax_C: 85; Cap_Case: 0805; SizeArea_mm2: 2.5; SizeAreaWB_mm2: 6.75; SizeX_mm: 2; SizeY_mm: 1.25; SizeZ_mm: 1.45; AEC Category: Q200
C35 C41 C50 C57 = C3216X5R1E476M160AC: as C31 on sheet TIDA-01458-Sheet1
C36 C42 C44 C52 C54 C55 = C1608X7R1H104K080AA: as C12 on sheet TIDA-01458-Sheet1
C38 C46 C48 C53 C59-C61 = C1608X5R1H105K080AB: as C11 on sheet TIDA-01458-Sheet1
D5-D8 = B260A-13-F: Diode, Schottky, 60 V, 2 A, SMA; Manufacturer: Diodes Inc.; U/M: EA; Vf_V: 0.7; Value: 60V; Value1: 2A; Value2: 0.7V; Io_A: 2; Vr_V: 60; TJmax_C: 150; RJC_CperW: 20; SizeAreaWB_mm2: 37.3428; SizeArea_mm2: 16.3228; SizeX_mm: 5.59; SizeY_mm: 2.92; SizeZ_mm: 2.87; AEC Category: Q101; Green_Lifecycle: Active; Green_REACh: Passed
J2 J3 = 1792876: Terminal Block, 5mm, 3x1, R/A, TH; Manufacturer: Phoenix Contact; SymbolCreator: a0412235; Pitch_mm: 5; Gender: Female; Row_Count: 1; Current_A: 16; Voltage_V: 400; Cert_UL: Y
J5-J8 = 901-144-8RFX: SMA Straight Jack, Gold, 50 Ohm, TH; Manufacturer: Amphenol RF; SymbolCreator: X0208326; Green_Lifecycle: Not Set; Green_REACh: Incomplete
R32 R35 R38 R41 R44-R46 R55 = CRCW0603100KFKEA: as R23 on sheet TIDA-01458-Sheet1
R33 R36 R37 R39 R42 R47 R48 R51 R54 R57 = CRCW060310K0FKEA: as R11 on sheet TIDA-01458-Sheet1
R34 R40 = CRCW0603330RJNEA: RES, 330, 5%, 0.1 W, 0603; Manufacturer: Vishay-Dale; CompType: Resistor; Value: 330; Value_Code: 330R; Tolerance_%: 5; Power_W: 0.1; Value2: 0.1W; VDC_V: 75; TempCo: 200 ppm/C; EIA_Code: E24; U/M: EA; AEC Category: Q200
R43 R52 = CRCW06031M20JNEA: RES, 1.2 M, 5%, 0.1 W, 0603; Manufacturer: Vishay-Dale; CompType: Resistor; Value: 1.2Meg; Res_ohm: 1200000; Value_Code: 1M20; Tolerance_%: 5; Power_W: 0.1; Value2: 0.1W; VDC_V: 75; TempCo: 200 ppm/C; EIA_Code: E24; U/M: EA; AEC Category: Q200
R50 R53 = CRCW0603120KJNEA: RES, 120 k, 5%, 0.1 W, 0603; Manufacturer: Vishay-Dale; CompType: Resistor; Value: 120k; Res_ohm: 120000; Tolerance_%: 5; Power_W: 0.1; Value2: 0.1W; VDC_V: 75; TempCo: 200 ppm/C; EIA_Code: E24; U/M: EA; AEC Category: Q200
R59-R63 = CRCW06030000Z0EA: as R2 on sheet TIDA-01458-Sheet1
U5 U6 = TPS7A4701RGWR: 36-V, 1-A, 4.17-uVRMS, RF LDO Voltage Regulator, RGW0020A (VQFN-20); Alternate PartNumber: TPS7A4701RGWT; Manufacturer: Texas Instruments; SymbolCreator: a0411947; SizeArea_mm2: 25; SizeAreaWB_mm2: 49; SizeX_mm: 5; SizeZ_mm: 1; CompType: IC; U/M: EA; Green_Lifecycle: Active; Green_REACh: Passed
U7 U9 = TLV2171IDR: as U2 on sheet TIDA-01458-Sheet1
U8 U10 = TPS7A3301RGWR: Single Output High PSRR LDO, 1 A, Adjustable -1.18 to -33 V Output, -3 to -36 V Input, with Ultra-Low Noise, 20-pin VQFN (RGW), -40 to 125 degC, Green (RoHS & no Sb/Br); Manufacturer: Texas Instruments; Alternate PartNumber: Equivalent; Accuracy(%): 1.5; Iout(Max)(A): 1; Iq(Typ)(mA): 0.21; SubFamily: Single Channel LDO; Vdo(Typ)(mV): 290

## Sheet TIDA-01458_Hardware.SchDoc: Hardware
size 431 x 279 mm; Date: Not shown in title block; ApprovedBy: Not shown in title block; CheckedBy: Not shown in title block; Author: Not shown in title block; CompanyName: Not shown in title block; DrawnBy: Sanjay Dixit; Engineer: Not shown in title block; Organization: Not shown in title block; Address1: Not shown in title block; Address2: Not shown in title block; Address3: Not shown in title block; Address4: Not shown in title block; DocumentNumber: 1; Revision: Use project parameter SCH_Rev; SheetNumber: 4; SheetTotal: 4; PageSetup: Record=PageOptions¦CenterHorizontal=True¦CenterVertical=True¦PrintScale=1.00¦XCorrection=1.00¦YCorrection=1.00¦PrintKind=0¦BorderSize=5000000¦LeftOffset=0¦BottomOffset=0¦Orientation=2¦PaperLength=1000¦PaperWidth=1000¦Scale=100¦PaperSource=15¦PrintQuality=600¦MediaType=1¦DitherType=10¦PaperKind=Letter¦PrintScaleMode=1
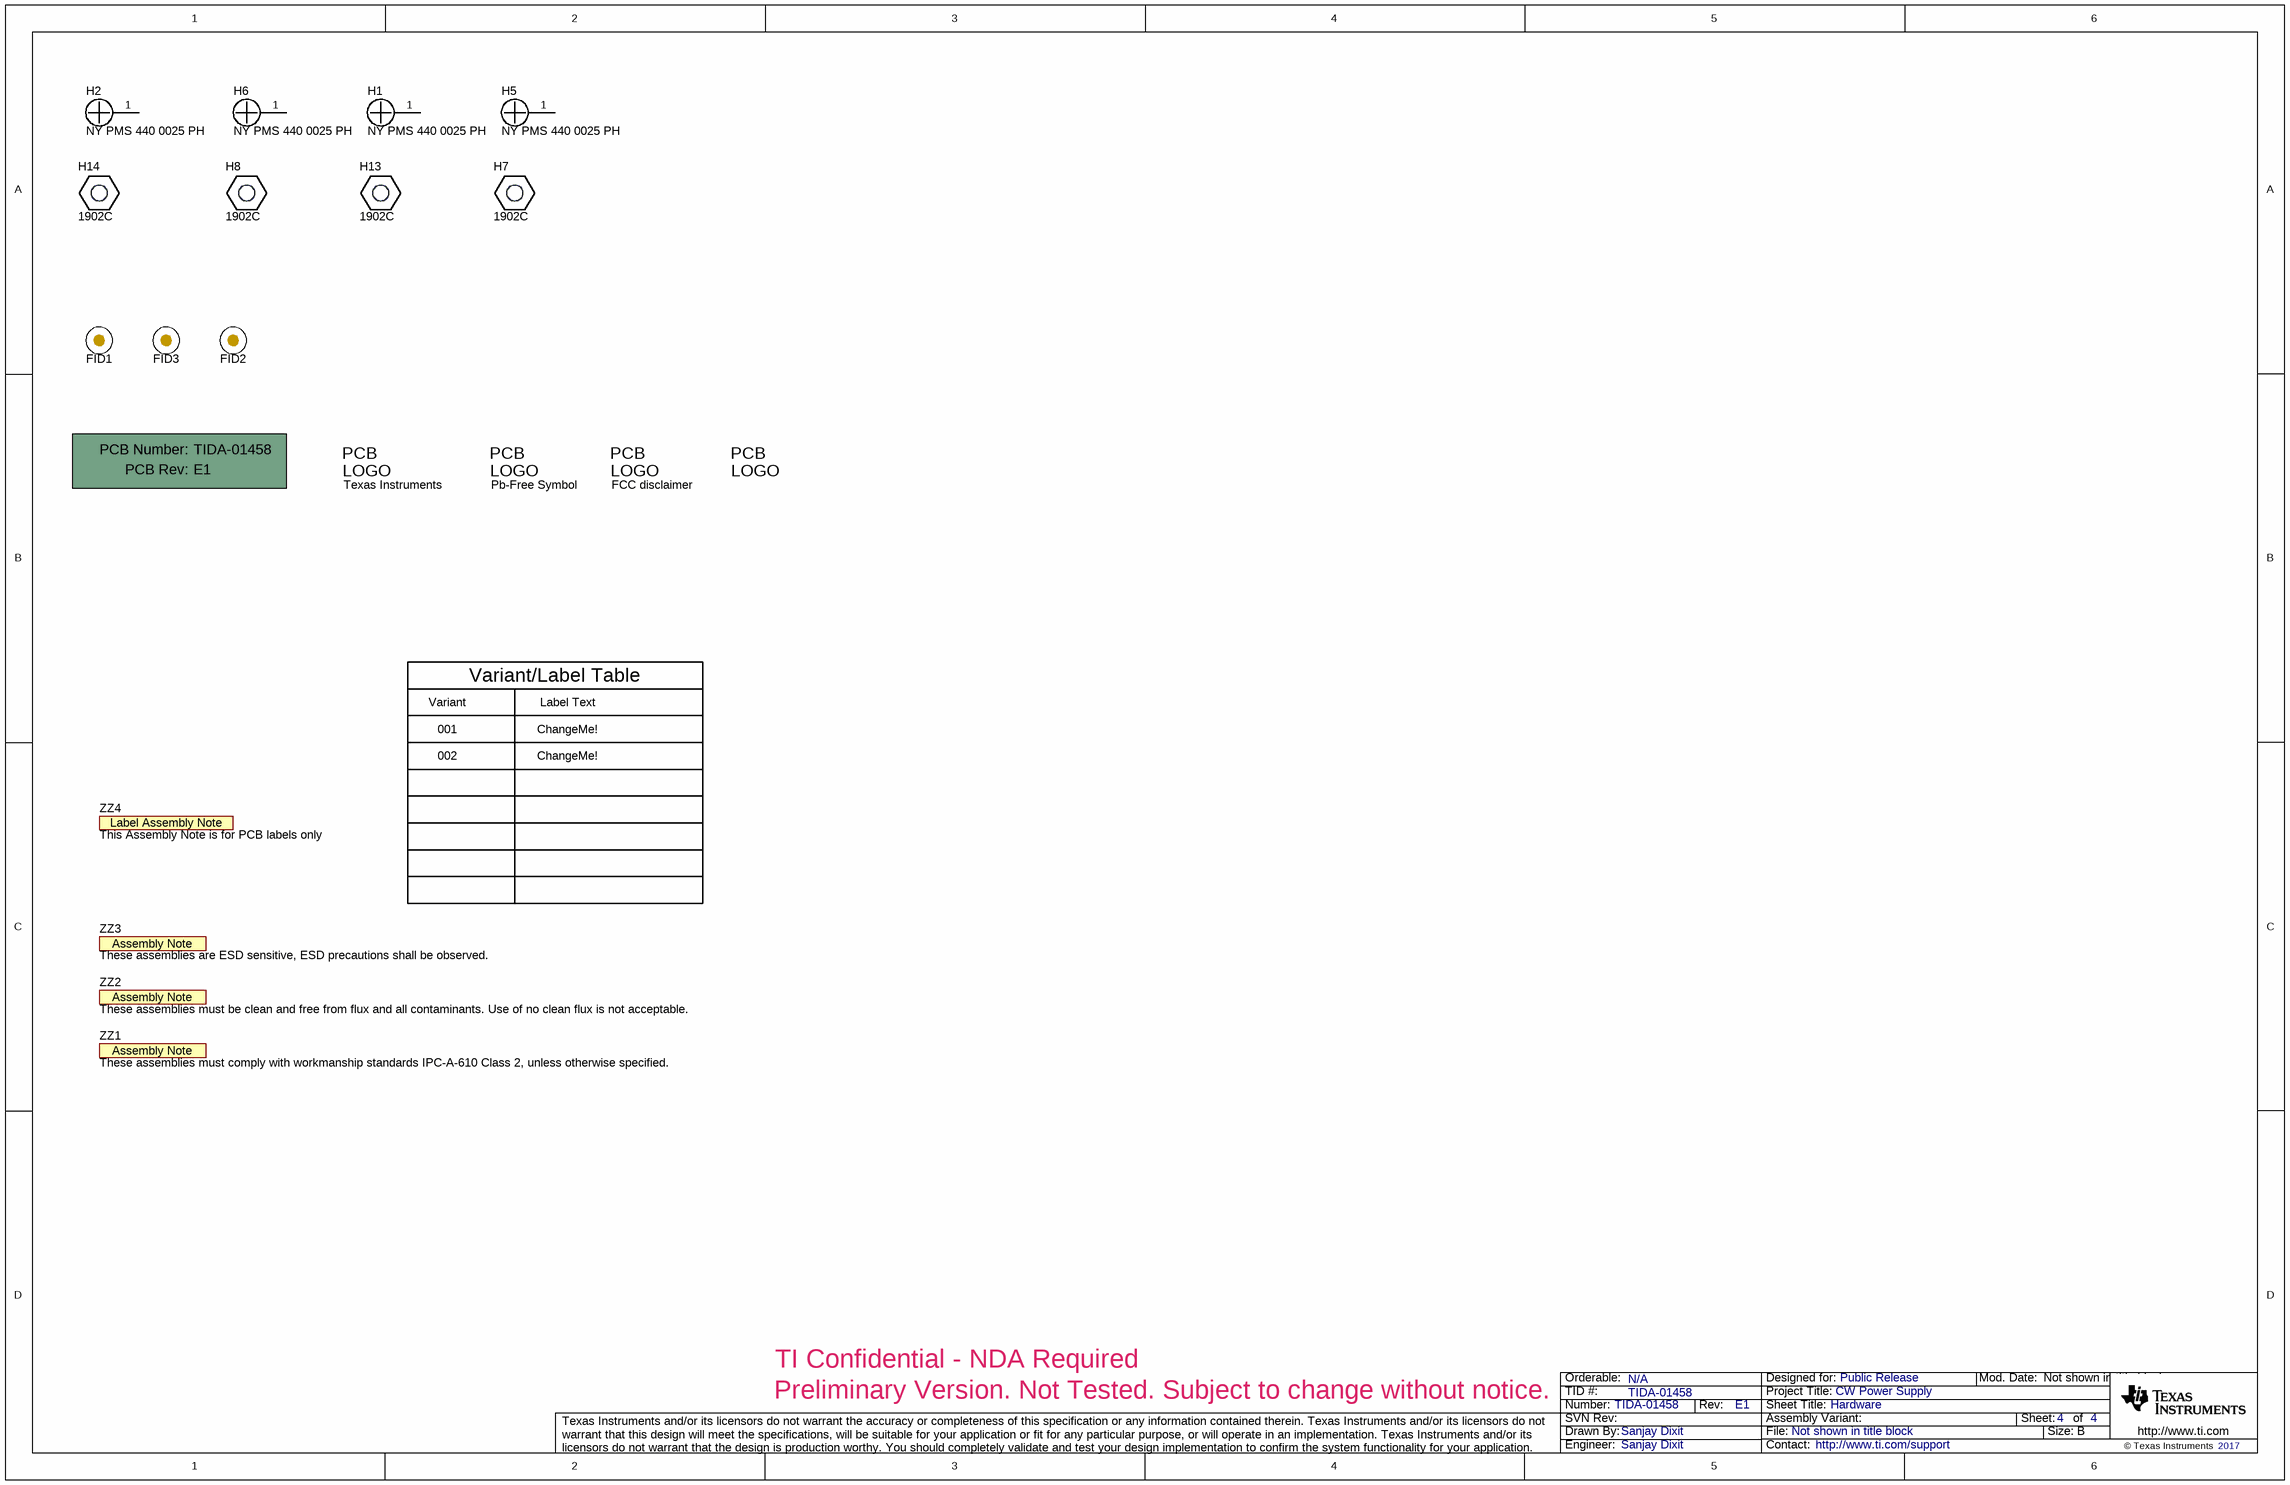
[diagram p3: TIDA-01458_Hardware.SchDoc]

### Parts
!PCB1  Printed Circuit Board  (value not drawn)  (mechanical)
FID1  Fiducial  [Fiducial10-20]  (value not drawn)
FID2  Fiducial  [Fiducial10-20]  (value not drawn)
FID3  Fiducial  [Fiducial10-20]  (value not drawn)
H1  NY PMS 440 0025 PH  [NY PMS 440 0025 PH]
H2  NY PMS 440 0025 PH  [NY PMS 440 0025 PH]
H5  NY PMS 440 0025 PH  [NY PMS 440 0025 PH]
H6  NY PMS 440 0025 PH  [NY PMS 440 0025 PH]
H7  1902C  [Keystone_1902C]
H8  1902C  [Keystone_1902C]
H13  1902C  [Keystone_1902C]
H14  1902C  [Keystone_1902C]
Logo1  ESD Susceptible  [ESD_Overlay_Small]  (value not drawn)  (no BOM)
Logo2  Pb-Free Symbol  [Pb-Free_Overlay_Small]  (no BOM)
Logo3  FCC disclaimer  [FCC_disclaimer]  (no BOM)
Logo4  Texas Instruments  [TI_Stacked_Overlay_Small]  (no BOM)
ZZ1  These assemblies must comply with workmanship standards IPC-A-610 Class 2, unless otherwise specified.  [AssemblyNote]  (no BOM)
ZZ2  These assemblies must be clean and free from flux and all contaminants. Use of no clean flux is not acceptable.  [AssemblyNote]  (no BOM)
ZZ3  These assemblies are ESD sensitive, ESD precautions shall be observed.  [AssemblyNote]  (no BOM)
ZZ4  This Assembly Note is for PCB labels only  [AssemblyNoteLabel]  (no BOM)

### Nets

Not connected (* = marked no-connect by the designer): H1 1; H2 1; H5 1; H6 1

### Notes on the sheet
- Variant
- Variant/Label Table
- Label Text
- 001
- 002
- ChangeMe!
- TI Confidential - NDA Required
- Preliminary Version. Not Tested. Subject to change without notice.

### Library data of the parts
!PCB1 = PCB: Manufacturer: Any; PartNumber: TIDA-01458; SymbolCreator: a0412235
FID1-FID3 = Fiducial: Fiducial mark.  There is nothing to buy or mount.; SymbolCreator: codlsc
H1 H2 H5 H6 = NY PMS 440 0025 PH: Machine Screw, Round, #4-40 x 1/4, Nylon, Philips panhead; Manufacturer: B&F Fastener Supply; CompType: Hardware; SymbolCreator: codlsc; U/M: EA
H7 H8 H13 H14 = 1902C: Standoff, Hex, 0.5"L #4-40 Nylon; Manufacturer: Keystone; CompType: Hardware
Logo1 = ESD_Susceptible: ESD Susceptible Symbol; SymbolCreator: a0412235
Logo2 = Pb-Free: SymbolCreator: a0412235
Logo3 = FCC_disclaimer: SymbolCreator: codlsc
Logo4 = TI_Logo: Texas Instrument Corporate Signature; SymbolCreator: codlsc
ZZ1-ZZ3 = AssemblyNote: SymbolCreator: codlsc
ZZ4 = AssemblyNoteLabel: SymbolCreator: a0412235

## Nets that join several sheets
16V: TIDA-01458-Sheet1 (6 pins), TIDA-01458_Sheet2 (C44.1 C52.1 U7.8 U9.8)
+Vo: TIDA-01458-Sheet1 (8 pins), TIDA-01458_Sheet2 (11 pins)
-3.3V: TIDA-01458-Sheet1 (C33.1 D4.2 R29.1), TIDA-01458_Sheet2 (C55.1 U9.4)
-Vo: TIDA-01458-Sheet1 (13 pins), TIDA-01458_Sheet2 (10 pins)
AGND: TIDA-01458-Sheet1 (9 pins), TIDA-01458_Sheet2 (31 pins)
AGND1: TIDA-01458-Sheet1 (8 pins), TIDA-01458_Sheet2 (R63.1)
PGND_A: TIDA-01458-Sheet1 (32 pins), TIDA-01458_Sheet2 (R59.1)
PGND_B: TIDA-01458-Sheet1 (12 pins), TIDA-01458_Sheet2 (R60.1)
A: TIDA-01458-Sheet1 (R20.2), TIDA-01458_Sheet2 (R50.2)
B: TIDA-01458-Sheet1 (R17.2), TIDA-01458_Sheet2 (R41.2)

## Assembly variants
001: not fitted FID1 FID2 FID3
